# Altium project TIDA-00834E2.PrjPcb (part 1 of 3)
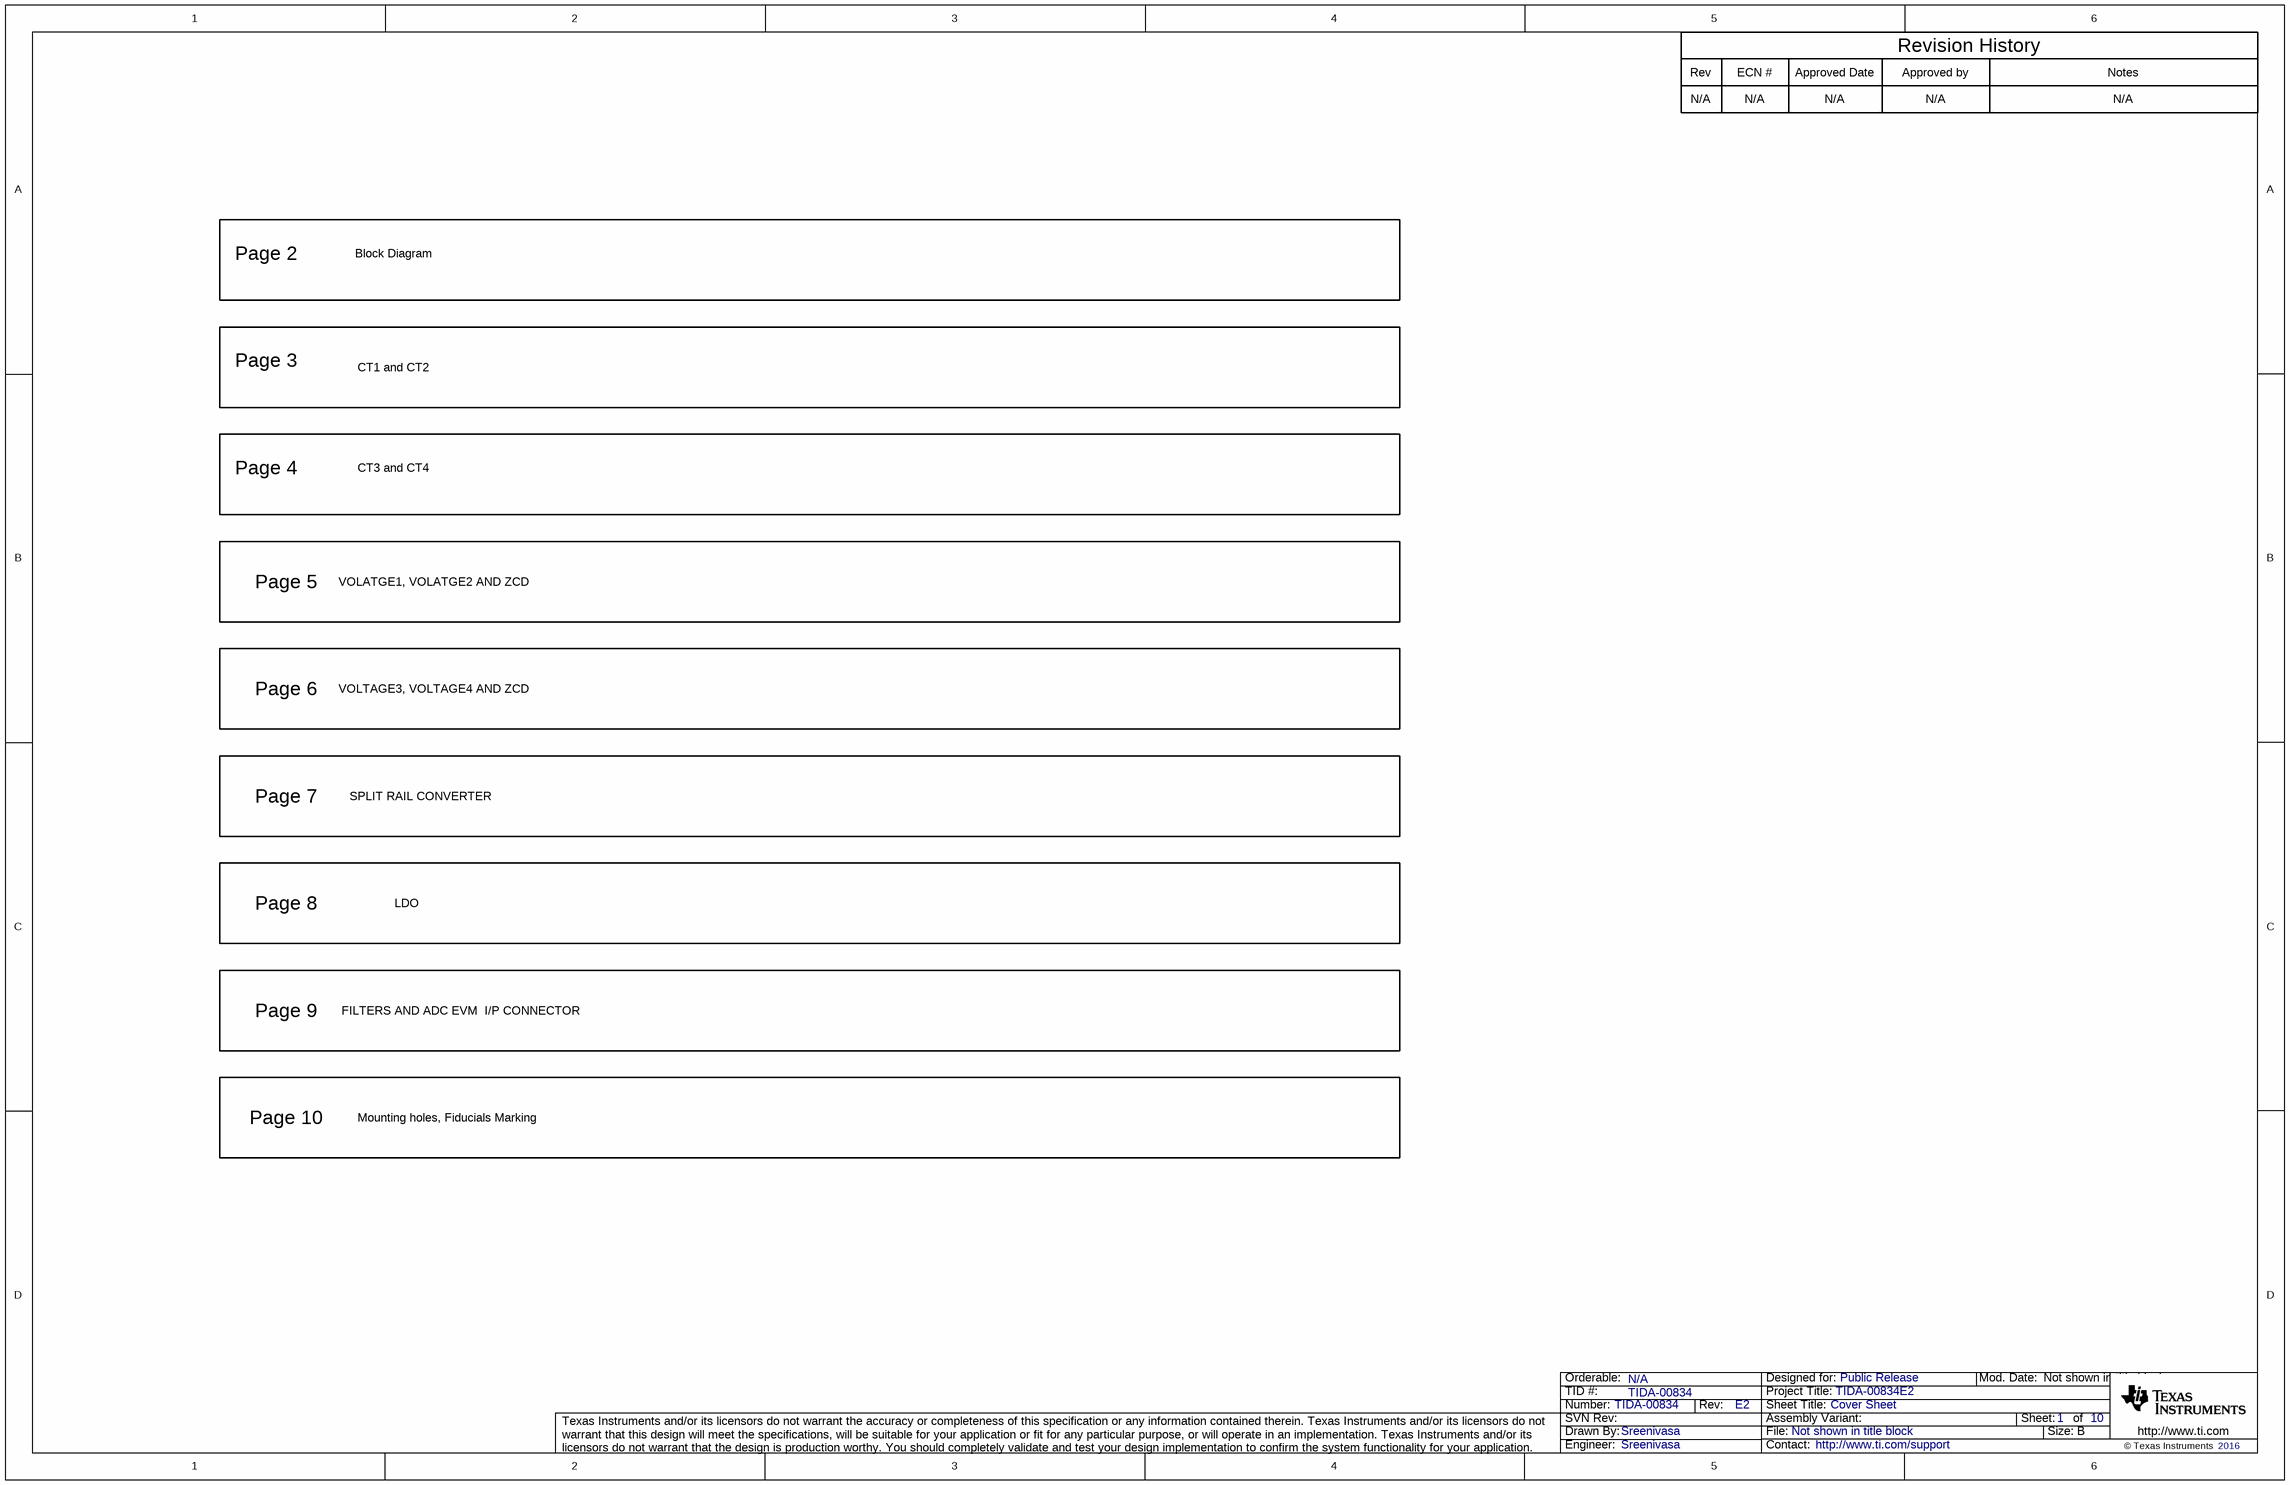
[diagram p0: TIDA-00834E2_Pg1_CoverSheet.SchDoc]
CopyrightYear: 2016; EVM_Orderable: N/A; PCB_Layout: Manjunath M; PCB_Rev: E2; PRJ_Customer: Public Release; PRJ_Engineer: Sreenivasa; PRJ_Number: TIDA-00834; PRJ_Title: TIDA-00834E2; SCH_Rev: E2; TechSupport: http://www.ti.com/support; TID: TIDA-00834
10 sheets, 589 parts. Net scope: flat (ports and power ports of the same name join across sheets).
Board file: TIDA-00834E2_PCB.PcbDoc
Sheets:
  TIDA-00834E2_Pg1_CoverSheet.SchDoc
  TIDA-00834E2_Pg2_Block Diagram.SchDoc
  TIDA-00834E2_Pg3_CT1_CT2.SchDoc
  TIDA-00834E2_Pg4_CT3_CT4.SchDoc
  TIDA-00834E2_Pg5_VOLTAGE.SchDoc
  TIDA-00834E2_Pg6_VOLTAGE2.SchDoc
  TIDA-00834E2_Pg7_Split Rail Converter.SchDoc
  TIDA-00834E2_Pg8_LDO.SchDoc
  TIDA-00834E2_Pg9_Filters.SchDoc
  TIDA-00834E2_Pg10_EVM_Hardware.SchDoc

## Sheet TIDA-00834E2_Pg1_CoverSheet.SchDoc: Cover Sheet
size 431 x 279 mm; Date: Not shown in title block; ApprovedBy: Not shown in title block; CheckedBy: Not shown in title block; Author: Not shown in title block; CompanyName: Not shown in title block; DrawnBy: Sreenivasa; Engineer: Not shown in title block; Organization: Not shown in title block; Address1: Not shown in title block; Address2: Not shown in title block; Address3: Not shown in title block; Address4: Not shown in title block; DocumentNumber: 1; Revision: Use project parameter SCH_Rev; SheetNumber: 1; SheetTotal: 10; PageSetup: Record=PageOptions¦CenterHorizontal=True¦CenterVertical=True¦PrintScale=1.00¦XCorrection=1.00¦YCorrection=1.00¦PrintKind=0¦BorderSize=5000000¦LeftOffset=0¦BottomOffset=0¦Orientation=2¦PaperLength=1000¦PaperWidth=1000¦Scale=100¦PaperSource=15¦PrintQuality=600¦MediaType=1¦DitherType=10¦PaperKind=Letter¦PrintScaleMode=1

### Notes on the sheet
- Rev
- N/A
- ECN #
- Approved Date
- Approved by
- Revision History
- Notes
- Page 2
- Block Diagram
- Page 3
- CT1 and CT2
- Page 4
- CT3 and CT4
- Page 5
- VOLATGE1, VOLATGE2 AND ZCD
- Page 6
- VOLTAGE3, VOLTAGE4 AND ZCD
- Page 7
- SPLIT RAIL CONVERTER
- Page 8
- LDO
- Page 9
- FILTERS AND ADC EVM  I/P CONNECTOR
- Page 10
- Mounting holes, Fiducials Marking

## Sheet TIDA-00834E2_Pg2_Block Diagram.SchDoc: Block Diagram
size 431 x 279 mm; Date: Not shown in title block; ApprovedBy: Not shown in title block; CheckedBy: Not shown in title block; Author: Not shown in title block; CompanyName: Not shown in title block; DrawnBy: Sreenivasa; Engineer: Not shown in title block; Organization: Not shown in title block; Address1: Not shown in title block; Address2: Not shown in title block; Address3: Not shown in title block; Address4: Not shown in title block; DocumentNumber: 1; Revision: Use project parameter SCH_Rev; SheetNumber: 2; SheetTotal: 10; PageSetup: Record=PageOptions¦CenterHorizontal=True¦CenterVertical=True¦PrintScale=1.00¦XCorrection=1.00¦YCorrection=1.00¦PrintKind=0¦BorderSize=5000000¦LeftOffset=0¦BottomOffset=0¦Orientation=2¦PaperLength=1000¦PaperWidth=1000¦Scale=100¦PaperSource=15¦PrintQuality=600¦MediaType=1¦DitherType=10¦PaperKind=Letter¦PrintScaleMode=1
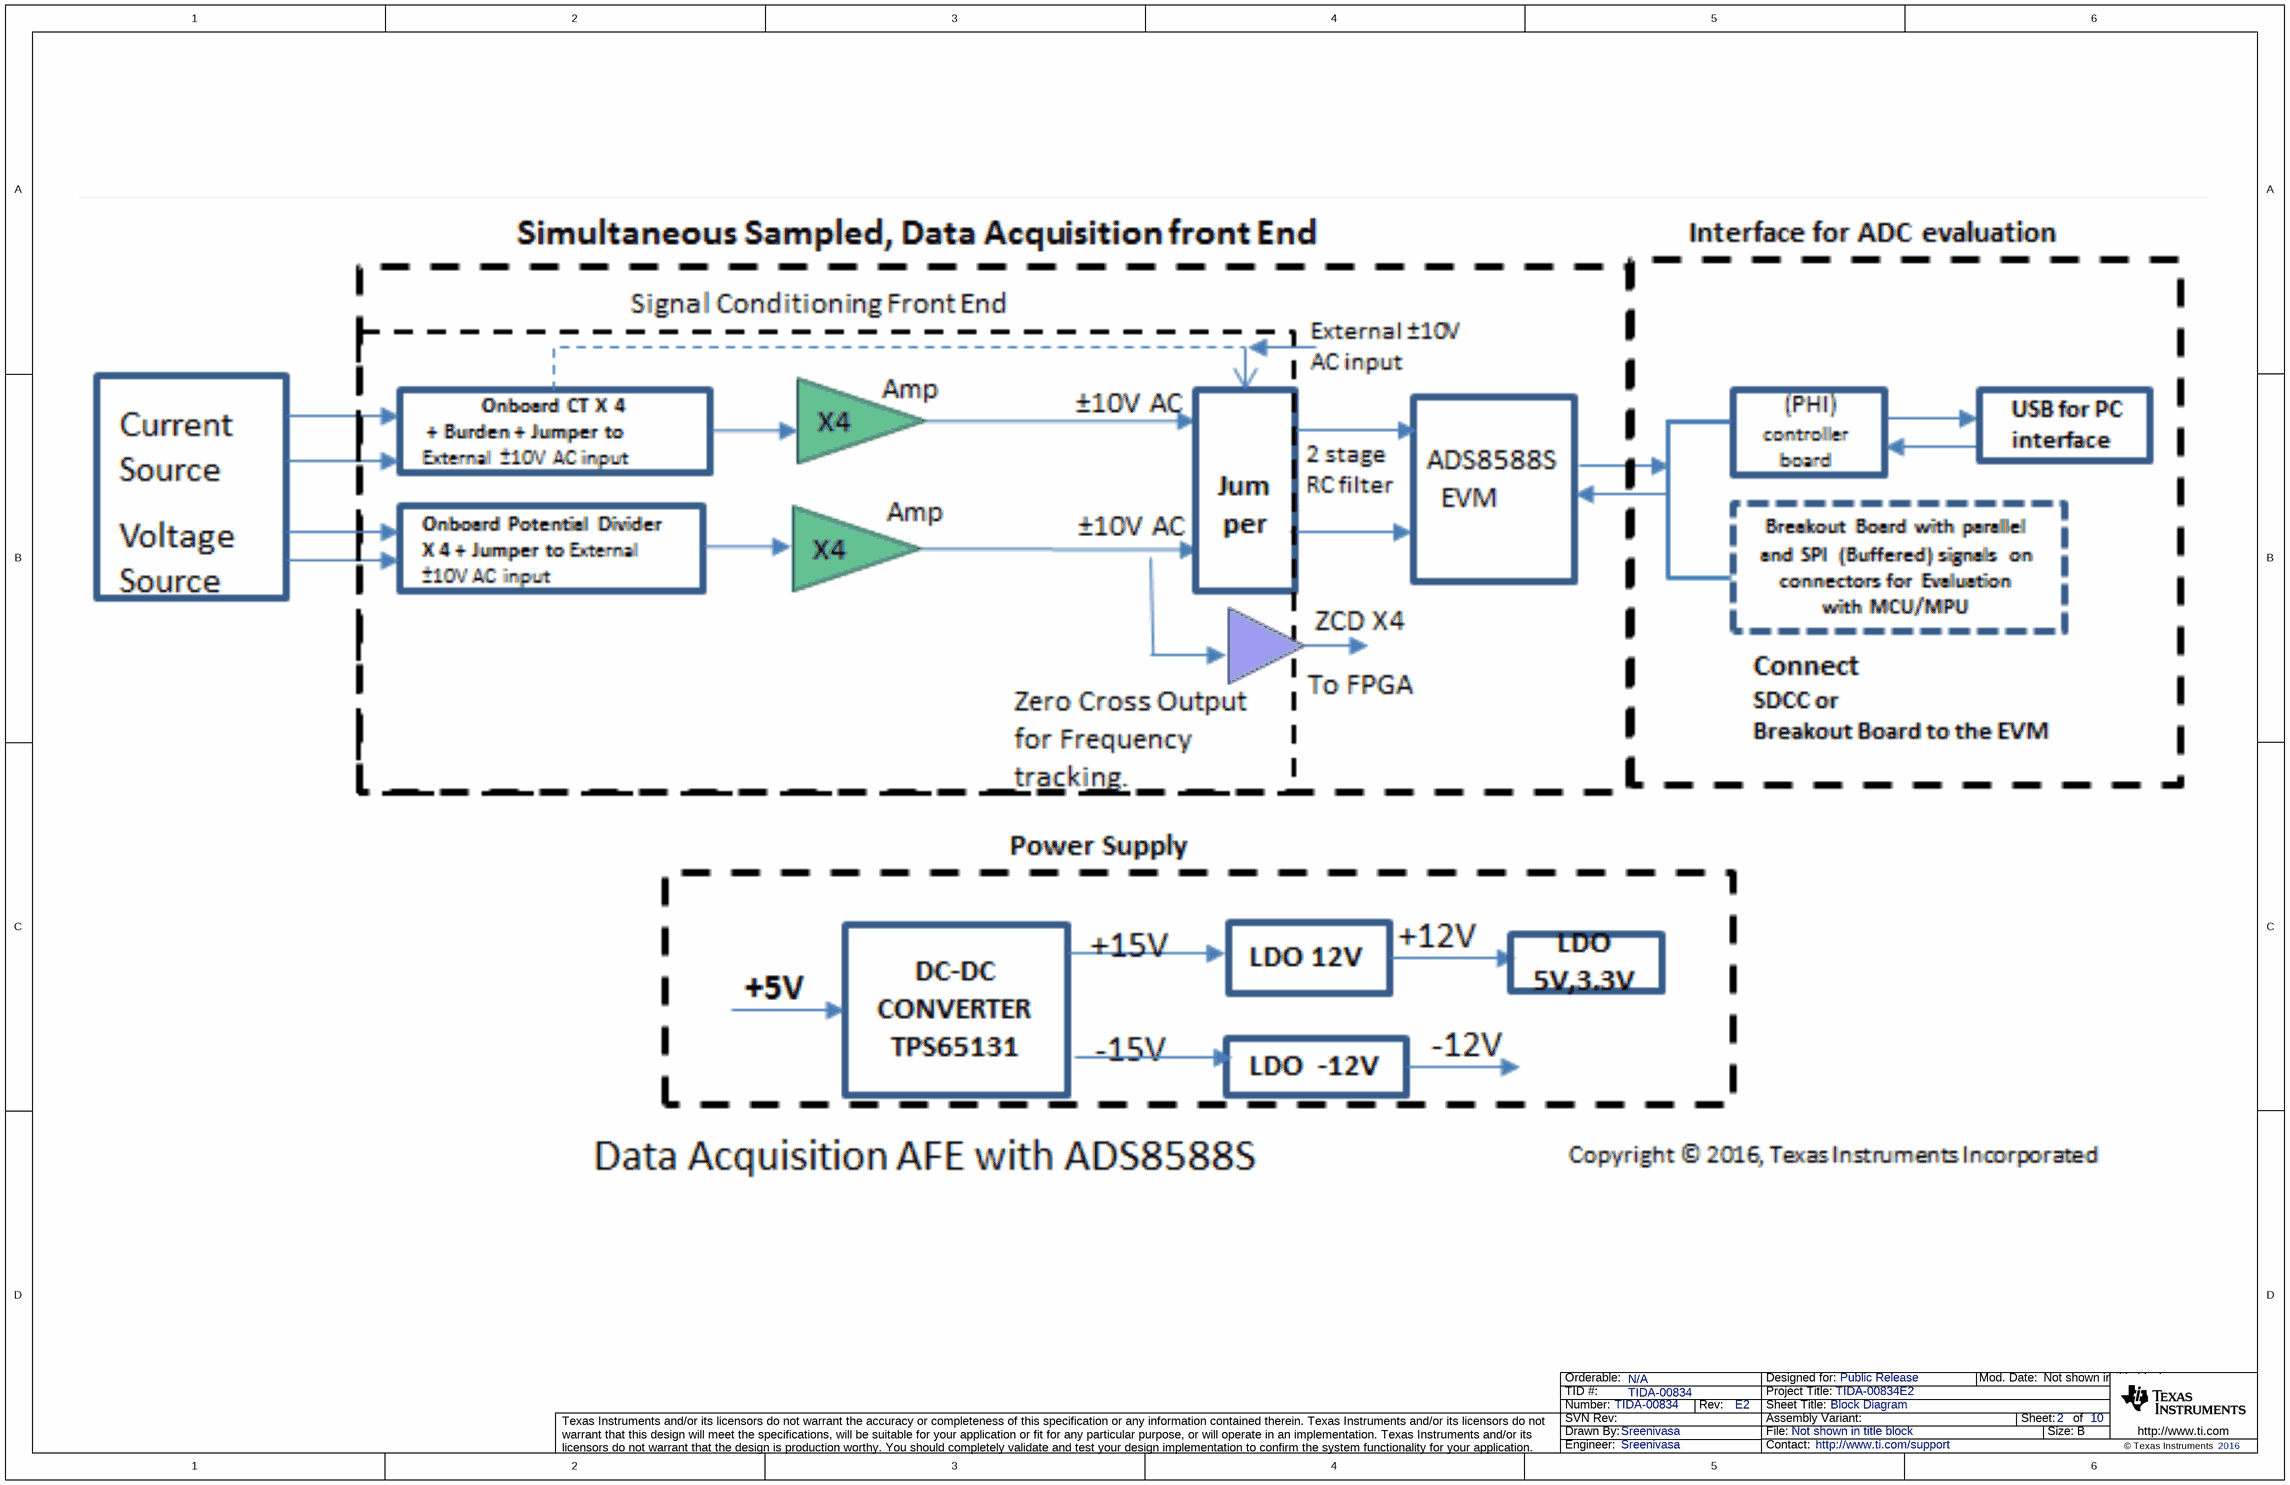
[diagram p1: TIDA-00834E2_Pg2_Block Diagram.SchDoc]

## Sheet TIDA-00834E2_Pg3_CT1_CT2.SchDoc: CT1 and CT2
size 431 x 279 mm; Date: Not shown in title block; ApprovedBy: Not shown in title block; CheckedBy: Not shown in title block; Author: Not shown in title block; CompanyName: Not shown in title block; DrawnBy: Sreenivasa; Engineer: Not shown in title block; Organization: Not shown in title block; Address1: Not shown in title block; Address2: Not shown in title block; Address3: Not shown in title block; Address4: Not shown in title block; DocumentNumber: 1; Revision: Use project parameter SCH_Rev; SheetNumber: 3; SheetTotal: 10; PageSetup: Record=PageOptions¦CenterHorizontal=True¦CenterVertical=True¦PrintScale=1.00¦XCorrection=1.00¦YCorrection=1.00¦PrintKind=0¦BorderSize=5000000¦LeftOffset=0¦BottomOffset=0¦Orientation=2¦PaperLength=1000¦PaperWidth=1000¦Scale=100¦PaperSource=15¦PrintQuality=600¦MediaType=1¦DitherType=10¦PaperKind=Letter¦PrintScaleMode=1
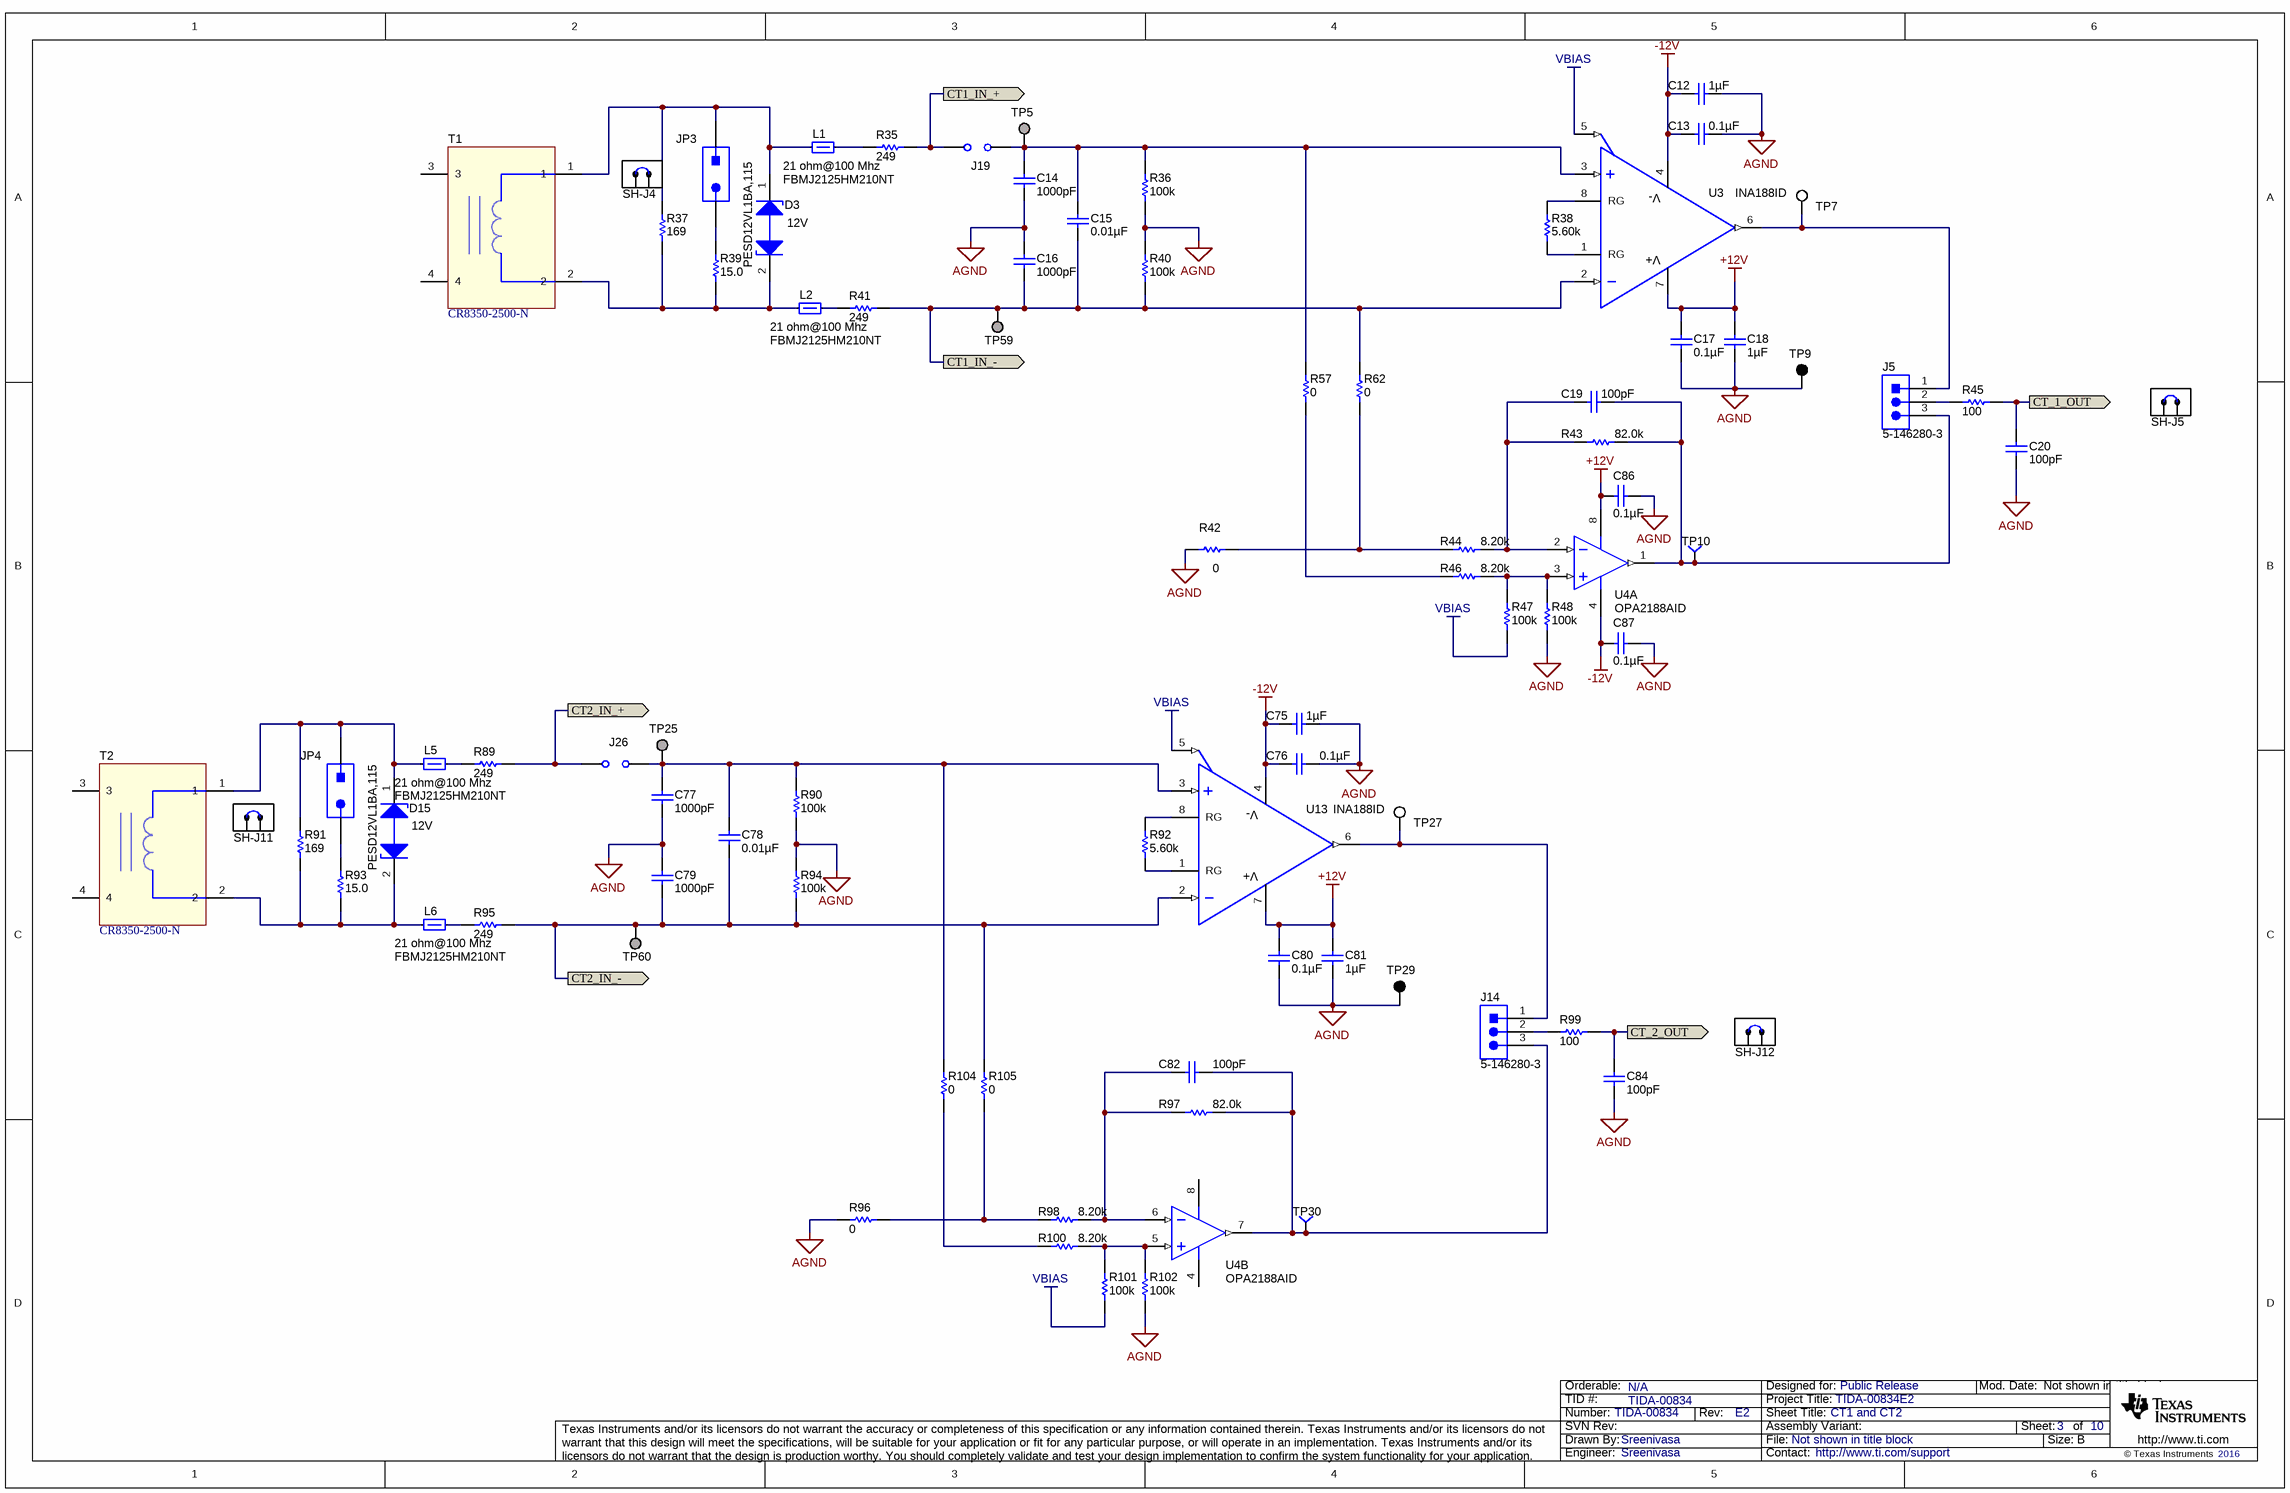
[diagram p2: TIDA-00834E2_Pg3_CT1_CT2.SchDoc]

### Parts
C12  ValueDisplayed: 1µF  [0603]  (hidden comment: GRM188R61C105KA93D)
C13  ValueDisplayed: 0.1µF  [0603]  (hidden comment: CGA3E2X8R1E104K080AA)
C14  ValueDisplayed: 1000pF  [0603]  (hidden comment: C0603X102K5RACTU)
C15  ValueDisplayed: 0.01µF  [0603]  (hidden comment: 06031C103KAT2A)
C16  ValueDisplayed: 1000pF  [0603]  (hidden comment: C0603X102K5RACTU)
C17  ValueDisplayed: 0.1µF  [0603]  (hidden comment: CGA3E2X8R1E104K080AA)
C18  ValueDisplayed: 1µF  [0603]  (hidden comment: GRM188R61C105KA93D)
C19  ValueDisplayed: 100pF  [0603]  (hidden comment: 06033C101KAT2A)
C20  ValueDisplayed: 100pF  [0603]  (hidden comment: 06033C101KAT2A)
C75  ValueDisplayed: 1µF  [0603]  (hidden comment: GRM188R61C105KA93D)
C76  ValueDisplayed: 0.1µF  [0603]  (hidden comment: CGA3E2X8R1E104K080AA)
C77  ValueDisplayed: 1000pF  [0603]  (hidden comment: C0603X102K5RACTU)
C78  ValueDisplayed: 0.01µF  [0603]  (hidden comment: 06031C103KAT2A)
C79  ValueDisplayed: 1000pF  [0603]  (hidden comment: C0603X102K5RACTU)
C80  ValueDisplayed: 0.1µF  [0603]  (hidden comment: CGA3E2X8R1E104K080AA)
C81  ValueDisplayed: 1µF  [0603]  (hidden comment: GRM188R61C105KA93D)
C82  ValueDisplayed: 100pF  [0603]  (hidden comment: 06033C101KAT2A)
C84  ValueDisplayed: 100pF  [0603]  (hidden comment: 06033C101KAT2A)
C86  ValueDisplayed: 0.1µF  [0603]  (hidden comment: CGA3E2X8R1E104K080AA)
C87  ValueDisplayed: 0.1µF  [0603]  (hidden comment: CGA3E2X8R1E104K080AA)
D3  value 12V  [SOD-323]  (hidden comment: PESD12VL1BA,115)
D15  value 12V  [SOD-323]  (hidden comment: PESD12VL1BA,115)
J5  5-146280-3  [TE_5-146280-3]
J14  5-146280-3  [TE_5-146280-3]
J19  JUMPER_2X100MIL  [HDR100_1X2]  (value not drawn)
J26  JUMPER_2X100MIL  [HDR100_1X2]  (value not drawn)
JP3  5-146280-2  [TSW-102-07-G-S]  (value not drawn)
JP4  5-146280-2  [TSW-102-07-G-S]  (value not drawn)
L1  value 21 ohm@100 Mhz  [0805_HV]  (hidden comment: FBMJ2125HM210NT)
L2  value 21 ohm@100 Mhz  [0805_HV]  (hidden comment: FBMJ2125HM210NT)
L5  value 21 ohm@100 Mhz  [0805_HV]  (hidden comment: FBMJ2125HM210NT)
L6  value 21 ohm@100 Mhz  [0805_HV]  (hidden comment: FBMJ2125HM210NT)
R35  ValueDisplayed: 249  [0603]  (hidden comment: RT0603BRD07249RL)
R36  ValueDisplayed: 100k  [0603]  (hidden comment: RC0603FR-07100KL)
R37  ValueDisplayed: 169  [0603]  (hidden comment: RC0603FR-07169RL)
R38  ValueDisplayed: 5.60k  [0603]  (hidden comment: RG1608P-562-B-T5)
R39  ValueDisplayed: 15.0  [0603]  (hidden comment: CRCW060315R0FKEA)
R40  ValueDisplayed: 100k  [0603]  (hidden comment: RC0603FR-07100KL)
R41  ValueDisplayed: 249  [0603]  (hidden comment: RT0603BRD07249RL)
R42  ValueDisplayed: 0  [0603]  (hidden comment: RC0603JR-070RL)
R43  ValueDisplayed: 82.0k  [0603]  (hidden comment: RG1608P-823-B-T5)
R44  ValueDisplayed: 8.20k  [0603]  (hidden comment: RC0603FR-078K2L)
R45  value 100  [0603]  (hidden comment: CRCW0603100RFKEA)
R46  ValueDisplayed: 8.20k  [0603]  (hidden comment: RC0603FR-078K2L)
R47  ValueDisplayed: 100k  [0603]  (hidden comment: RC0603FR-07100KL)
R48  ValueDisplayed: 100k  [0603]  (hidden comment: RC0603FR-07100KL)
R57  ValueDisplayed: 0  [0603]  (hidden comment: RC0603JR-070RL)
R62  ValueDisplayed: 0  [0603]  (hidden comment: RC0603JR-070RL)
R89  ValueDisplayed: 249  [0603]  (hidden comment: RT0603BRD07249RL)
R90  ValueDisplayed: 100k  [0603]  (hidden comment: RC0603FR-07100KL)
R91  ValueDisplayed: 169  [0603]  (hidden comment: RC0603FR-07169RL)
R92  ValueDisplayed: 5.60k  [0603]  (hidden comment: RG1608P-562-B-T5)
R93  ValueDisplayed: 15.0  [0603]  (hidden comment: CRCW060315R0FKEA)
R94  ValueDisplayed: 100k  [0603]  (hidden comment: RC0603FR-07100KL)
R95  ValueDisplayed: 249  [0603]  (hidden comment: RT0603BRD07249RL)
R96  ValueDisplayed: 0  [0603]  (hidden comment: RC0603JR-070RL)
R97  ValueDisplayed: 82.0k  [0603]  (hidden comment: RG1608P-823-B-T5)
R98  ValueDisplayed: 8.20k  [0603]  (hidden comment: RC0603FR-078K2L)
R99  value 100  [0603]  (hidden comment: CRCW0603100RFKEA)
R100  ValueDisplayed: 8.20k  [0603]  (hidden comment: RC0603FR-078K2L)
R101  ValueDisplayed: 100k  [0603]  (hidden comment: RC0603FR-07100KL)
R102  ValueDisplayed: 100k  [0603]  (hidden comment: RC0603FR-07100KL)
R104  ValueDisplayed: 0  [0603]  (hidden comment: RC0603JR-070RL)
R105  ValueDisplayed: 0  [0603]  (hidden comment: RC0603JR-070RL)
SH-J4  881545-2  [TE_881545-2]  (value not drawn)  (mechanical)
SH-J5  881545-2  [TE_881545-2]  (value not drawn)  (mechanical)
SH-J11  881545-2  [TE_881545-2]  (value not drawn)  (mechanical)
SH-J12  881545-2  [TE_881545-2]  (value not drawn)  (mechanical)
T1  CR8350-2500-N  [XFMR_CR8350-2500-N]
T2  CR8350-2500-N  [XFMR_CR8350-2500-N]
TP5  Suggest using a net name here  [Keystone1573-2]  (value not drawn)
TP7  5002  [Keystone5002]  (value not drawn)
TP9  5001  [Keystone5001]  (value not drawn)
TP10  TP-040_RND  [TP_H045P075]  (value not drawn)
TP25  Suggest using a net name here  [Keystone1573-2]  (value not drawn)
TP27  5002  [Keystone5002]  (value not drawn)
TP29  5001  [Keystone5001]  (value not drawn)
TP30  TP-040_RND  [TP_H045P075]  (value not drawn)
TP59  Suggest using a net name here  [Keystone1573-2]  (value not drawn)
TP60  Suggest using a net name here  [Keystone1573-2]  (value not drawn)
U3  INA188ID  [D0008A_N]
U4  OPA2188AID  [D0008A_N]  (parts A,B of 2)
U13  INA188ID  [D0008A_N]

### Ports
CT1_IN_+ (out), CT1_IN_- (out), CT2_IN_+ (out), CT2_IN_- (out), CT_1_OUT (out), CT_2_OUT (out)

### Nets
+12V: C17.1 C18.1 C80.1 C81.1 C86.1 U3.7(V+) U4.8(V+) U13.7(V+)
-12V: C12.1 C13.1 C75.1 C76.1 C87.1 U3.4(V-) U4.4(V-) U13.4(V-)
AGND: C12.2 C13.2 C14.2 C16.1 C17.2 C18.2 C20.2 C75.2 C76.2 C77.2 C79.1 C80.2 C81.2 C84.2 C86.2 C87.2 R36.1 R40.2 R42.1 R48.1 R90.1 R94.2 R96.2 R102.1 TP9.1 TP29.1
VBIAS: R47.1 R101.1 U3.5(REF) U13.5(REF)
CT1_IN_+: J19.2 R35.2 ; port CT1_IN_+
CT1_IN_-: C15.2 C16.2 R40.1 R41.2 R62.2 TP59.1 U3.2(IN-) ; port CT1_IN_-
CT2_IN_+: J26.2 R89.2 ; port CT2_IN_+
CT2_IN_-: C78.2 C79.2 R94.1 R95.2 R105.2 TP60.1 U13.2(IN-) ; port CT2_IN_-
CT_1_OUT: C20.1 R45.2 ; port CT_1_OUT
CT_2_OUT: C84.1 R99.2 ; port CT_2_OUT
NetC14_1: C14.1 C15.1 J19.1 R36.2 R57.2 TP5.1 U3.3(IN+)
NetC19_1: C19.1 R43.2 R44.1 U4.2(IN_A-)
NetC19_2: C19.2 J5.3 R43.1 TP10.1 U4.1(OUT_A)
NetC77_1: C77.1 C78.1 J26.1 R90.2 R104.2 TP25.1 U13.3(IN+)
NetC82_1: C82.1 R97.2 R98.1 U4.6(IN_B-)
NetC82_2: C82.2 J14.3 R97.1 TP30.1 U4.7(OUT_B)
NetD3_1: D3.1(K) JP3.1 L1.1 R37.2 T1.1
NetD3_2: D3.2(K) L2.1 R37.1 R39.1 T1.2
NetD15_1: D15.1(K) JP4.1 L5.1 R91.2 T2.1
NetD15_2: D15.2(K) L6.1 R91.1 R93.1 T2.2
NetJ5_1: J5.1 TP7.1 U3.6(OUT)
NetJ5_2: J5.2 R45.1
NetJ14_1: J14.1 TP27.1 U13.6(OUT)
NetJ14_2: J14.2 R99.1
NetJP3_2: JP3.2 R39.2
NetJP4_2: JP4.2 R93.2
NetL1_2: L1.2 R35.1
NetL2_2: L2.2 R41.1
NetL5_2: L5.2 R89.1
NetL6_2: L6.2 R95.1
NetR38_1: R38.1 U3.1(RG)
NetR38_2: R38.2 U3.8(RG)
NetR42_2: R42.2 R44.2 R62.1
NetR46_1: R46.1 R47.2 R48.2 U4.3(IN_A+)
NetR46_2: R46.2 R57.1
NetR92_1: R92.1 U13.1(RG)
NetR92_2: R92.2 U13.8(RG)
NetR96_1: R96.1 R98.2 R105.1
NetR100_1: R100.1 R101.2 R102.2 U4.5(IN_B+)
NetR100_2: R100.2 R104.1

Not connected (* = marked no-connect by the designer): T1 3 4; T2 3 4

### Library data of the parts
C12 C18 C75 C81 = C1608X5R1C105K: CAP, CERM, 1 µF, 16 V, +/- 10%, X5R, 0603; Manufacturer: Murata; Polarized: N; CompType: Capacitor; Value: 1uF; U/M: EA; Cap_F: 0.000001; Tolerance_%: 10; ESR_ohm: 0.0057; Value1: 0.0057 ohm; VDC_V: 16; Value2: 16V; TaMin_C: -55; TaMax_C: 85; AEC Category: Q200
C13 C17 C76 C80 C86 C87 = CGA3E2X8R1E104K080AA: CAP, CERM, 0.1 µF, 25 V, +/- 10%, X8R, AEC-Q200 Grade 0, 0603; Manufacturer: TDK; Polarized: N; CompType: Capacitor; Value: 0.1uF; U/M: EA; Cap_F: 0.0000001; Tolerance_%: 10; Value1: Unknown; VDC_V: 25; Value2: 25V; TaMin_C: -55; TaMax_C: 150; AEC Category: Q200; AEC Qualified: Y; AEC Grade: 0
C14 C16 C77 C79 = C0603X102K5RACTU: CAP, CERM, 1000 pF, 50 V, +/- 10%, X7R, 0603; Manufacturer: Kemet; Polarized: N; CompType: Capacitor; Value: 1000pF; U/M: EA; Cap_F: 0.000000001; Tolerance_%: 10; Value1: Unknown; VDC_V: 50; Value2: 50V; TaMin_C: -55; TaMax_C: 125; AEC Category: Q200
C15 C78 = 06031C103JAT2A: 10000pF 100V Ceramic Capacitor X7R 0603; Manufacturer: AVX; Polarized: N; Value: 0.01uF; U/M: EA; Cap_F: 0.00000001; Tolerance_%: 5; ESR_ohm: 0.098; Value1: 0.098 ohm; VDC_V: 100; TaMin_C: -55; TaMax_C: 125; AEC Category: Q200
C19 C20 C82 C84 = 06033C101KAT2A: CAP, CERM, 100pF, 25V, +/-10%, X7R, 0603; Manufacturer: AVX; Polarized: N; CompType: Capacitor; U/M: EA; Cap_F: 0.0000000001; Tolerance_%: 10; Value1: Unknown; VDC_V: 25; TaMin_C: -55; TaMax_C: 125
D3 D15 = PESD3V3L1BA: TVS DIODE 12VWM 37VC SOD323; Manufacturer: NXP Semiconductor; SymbolCreator: x0199378
J5 J14 = 5-146280-3: Header, 2.54mm, 3x1, Gold, TH; Manufacturer: TE Connectivity; SymbolCreator: a0799628; Pitch_mm: 2.54; Gender: Male; Shrouded: N; Row_Count: 1
J19 J26 = JUMPER_2X100MIL: Header, Male 2-pin, 100mil spacing,; Manufacturer: Sullins; PartNumber: PEC02SAAN; area: 20000; Value: PEC02SAAN
JP3 JP4 = TSW-102-07-G-S: Header, 100mil, 2x1, Gold, TH; Manufacturer: TE Connectivity; SymbolCreator: a0412235; U/M: EA
L1 L2 L5 L6 = FBMJ2125HM210NT: Ferrite Bead, 21 ohm @ 100 MHz, 6 A, 0805; Manufacturer: Taiyo Yuden; Imax_A: 6; DCR_ohm: 0.004; Value1: 0.004 ohm; Value2: 6A; ZTyp@100MHz_Ohm: 21
R35 R41 R89 R95 = RT0603BRD07249RL: RES, 249, 0.1%, 0.1 W, 0603; Manufacturer: Yageo America; CompType: Resistor; Value: 249; Value_Code: 249R; Tolerance_%: 0.1; Value2: 0.1W; VDC_V: 75; TempCo: 25 ppm/C; EIA_Code: E192; U/M: EA; AEC Category: Q200
R36 R40 R47 R48 R90 R94 R101 R102 = RC0603FR-07100KL: RES, 100 k, 1%, 0.1 W, 0603; Manufacturer: Yageo America; CompType: Resistor; Value: 100k; Res_ohm: 100000; Tolerance_%: 1; Power_W: 0.1; Value2: 0.1W; VDC_V: 150; TempCo: 200 ppm/C; EIA_Code: E96; U/M: EA; AEC Category: Q200
R37 R91 = RC0603FR-07169RL: RES, 169, 1%, 0.1 W, 0603; Manufacturer: Yageo America; CompType: Resistor; Value: 169; Value_Code: 169R; Tolerance_%: 1; Power_W: 0.1; Value2: 0.1W; VDC_V: 150; TempCo: 200 ppm/C; SizeArea_mm2: 1.28; SizeX_mm: 1.6; SizeY_mm: 0.8; EIA_Code: E96; U/M: EA; AEC Category: Q200
R38 R92 = RG1608P-562-B-T5: RES, 5.60 k, 0.1%, 0.1 W, 0603; Manufacturer: Susumu Co Ltd; CompType: Resistor; Value: 5.60k; Res_ohm: 5600; Value_Code: 5k60; Tolerance_%: 0.1; Value2: 0.1W; VDC_V: 75; TempCo: 25 ppm/C; SizeArea_mm2: 1.28; SizeX_mm: 1.6; SizeY_mm: 0.8; SizeZ_mm: 1; U/M: EA; AEC Category: Q200
R39 R93 = CRCW060315R0FKEA: RES, 15.0, 1%, 0.1 W, 0603; Manufacturer: Vishay-Dale; CompType: Resistor; Value: 15.0; Res_ohm: 15; Value_Code: 15R0; Tolerance_%: 1; Power_W: 0.1; Value2: 0.1W; VDC_V: 75; TempCo: 100 ppm/C; SizeArea_mm2: 1.28; SizeX_mm: 1.6; SizeY_mm: 0.8; EIA_Code: E96; U/M: EA; AEC Category: Q200
R42 R57 R62 R96 R104 R105 = RC0603JR-070RL: RES, 0, 5%, 0.1 W, 0603; Manufacturer: Yageo America; CompType: Resistor; Value: 0; Value_Code: 0000; Tolerance_%: 5; Power_W: 0.1; Value2: 0.1W; VDC_V: 50; TempCo: 200 ppm/C; EIA_Code: E24; U/M: EA; AEC Category: Q200
R43 R97 = RG1608P-823-B-T5: RES, 82.0 k, 0.1%, 0.1 W, 0603; Manufacturer: Susumu Co Ltd; CompType: Resistor; Value: 82.0k; Res_ohm: 82000; Value_Code: 82k0; Tolerance_%: 0.1; Value2: 0.1W; VDC_V: 75; TempCo: 25 ppm/C; SizeArea_mm2: 1.28; SizeX_mm: 1.6; SizeY_mm: 0.8; SizeZ_mm: 1; U/M: EA; AEC Category: Q200
R44 R46 R98 R100 = RC0603FR-078K2L: RES, 8.20 k, 1%, 0.1 W, 0603; Manufacturer: Yageo America; CompType: Resistor; Value: 8.20k; Res_ohm: 8200; Value_Code: 8k20; Tolerance_%: 1; Power_W: 0.1; Value2: 0.1W; VDC_V: 150; TempCo: 200 ppm/C; U/M: EA; AEC Category: Q200
R45 R99 = CRCW0603100RFKEA: RES, 100 ohm, 1%, 0.1W, 0603; Manufacturer: Vishay-Dale; CompType: Resistor; Value_Code: 100R; Tolerance_%: 1; Power_W: 0.1; VDC_V: 75; TempCo: 100 ppm/C; EIA_Code: E96; U/M: EA
SH-J4 SH-J5 SH-J11 SH-J12 = 881545-2: Shunt, 100mil, Gold plated, Black; Manufacturer: TE Connectivity
T1 T2 = CR8350-2500-N: CURRENT TRANSFORMER, 20-1 KHz, 57 OHM, VERTICAL, THRU-4P; Manufacturer: CR MAGNETICS; SymbolCreator: x0199378
TP5 TP25 TP59 TP60 = 1573-2: Terminal, Turret, TH, Double; Manufacturer: Keystone; CompType: Turret Terminal; U/M: EA
TP7 TP27 = 5002: Test Point, Miniature, White, TH; Manufacturer: Keystone; CompType: Test Point Loop; U/M: EA
TP9 TP29 = 5001: Test Point, Miniature, Black, TH; Manufacturer: Keystone; CompType: Test Point Loop; U/M: EA
TP10 TP30 = TP-040_RND: Test Point, O.040 Hole; Manufacturer: STD; Value: STD
U3 U13 = INA188D: INA188 Precision, Zero-Drift, Rail-to-Rail Out, High Voltage Instrumentation Amplifier, D0008A; Manufacturer: Texas Instruments; SymbolCreator: Altium; CompType: IC; U/M: EA
U4 = OPA2188AID: 0.03 uV/degC, 6 uV Vos, Low Noise, Rail-to-Rail Output, Zero-Drift Operational Amplifier, 4 to 36 V, -40 to 105 degC, 8-pin SOIC (D0008A), Green (RoHS & no Sb/Br); Manufacturer: Texas Instruments; Alternate PartNumber: Equivalent; CMRR(Min)(dB): 120; GBW(Typ)(MHz): 2; IIB(Max)(pA): 850; Iq per channel(Max)(mA): 0.475; Offset Drift(Typ)(uV/C): 0.03; Packing: TUBE; Rating: Catalog; Slew Rate(Typ)(V/us): 0.8; Sub Family: High Supply Voltage Amplifier (>=30V), Low Noise Amp (<=10nV/rtHz), Low Offset Voltage Amplifier (<=500uV), Low Power Amp (<=500uA), Precision Amplifier, Zero Drift Precision Amplifier; Total Supply Voltage(Max)(+5V is 5, +/-5V is 10): 36; Total Supply Voltage(Min)(+5V is 5, +/-5V is 10): 4; Vio (25C)(Max)(mV): 0.025

## Sheet TIDA-00834E2_Pg4_CT3_CT4.SchDoc: CT3 and CT4
size 431 x 279 mm; Date: Not shown in title block; ApprovedBy: Not shown in title block; CheckedBy: Not shown in title block; Author: Not shown in title block; CompanyName: Not shown in title block; DrawnBy: Sreenivasa; Engineer: Not shown in title block; Organization: Not shown in title block; Address1: Not shown in title block; Address2: Not shown in title block; Address3: Not shown in title block; Address4: Not shown in title block; DocumentNumber: 1; Revision: Use project parameter SCH_Rev; SheetNumber: 4; SheetTotal: 10; PageSetup: Record=PageOptions¦CenterHorizontal=True¦CenterVertical=True¦PrintScale=1.00¦XCorrection=1.00¦YCorrection=1.00¦PrintKind=0¦BorderSize=5000000¦LeftOffset=0¦BottomOffset=0¦Orientation=2¦PaperLength=1000¦PaperWidth=1000¦Scale=100¦PaperSource=15¦PrintQuality=600¦MediaType=1¦DitherType=10¦PaperKind=Letter¦PrintScaleMode=1
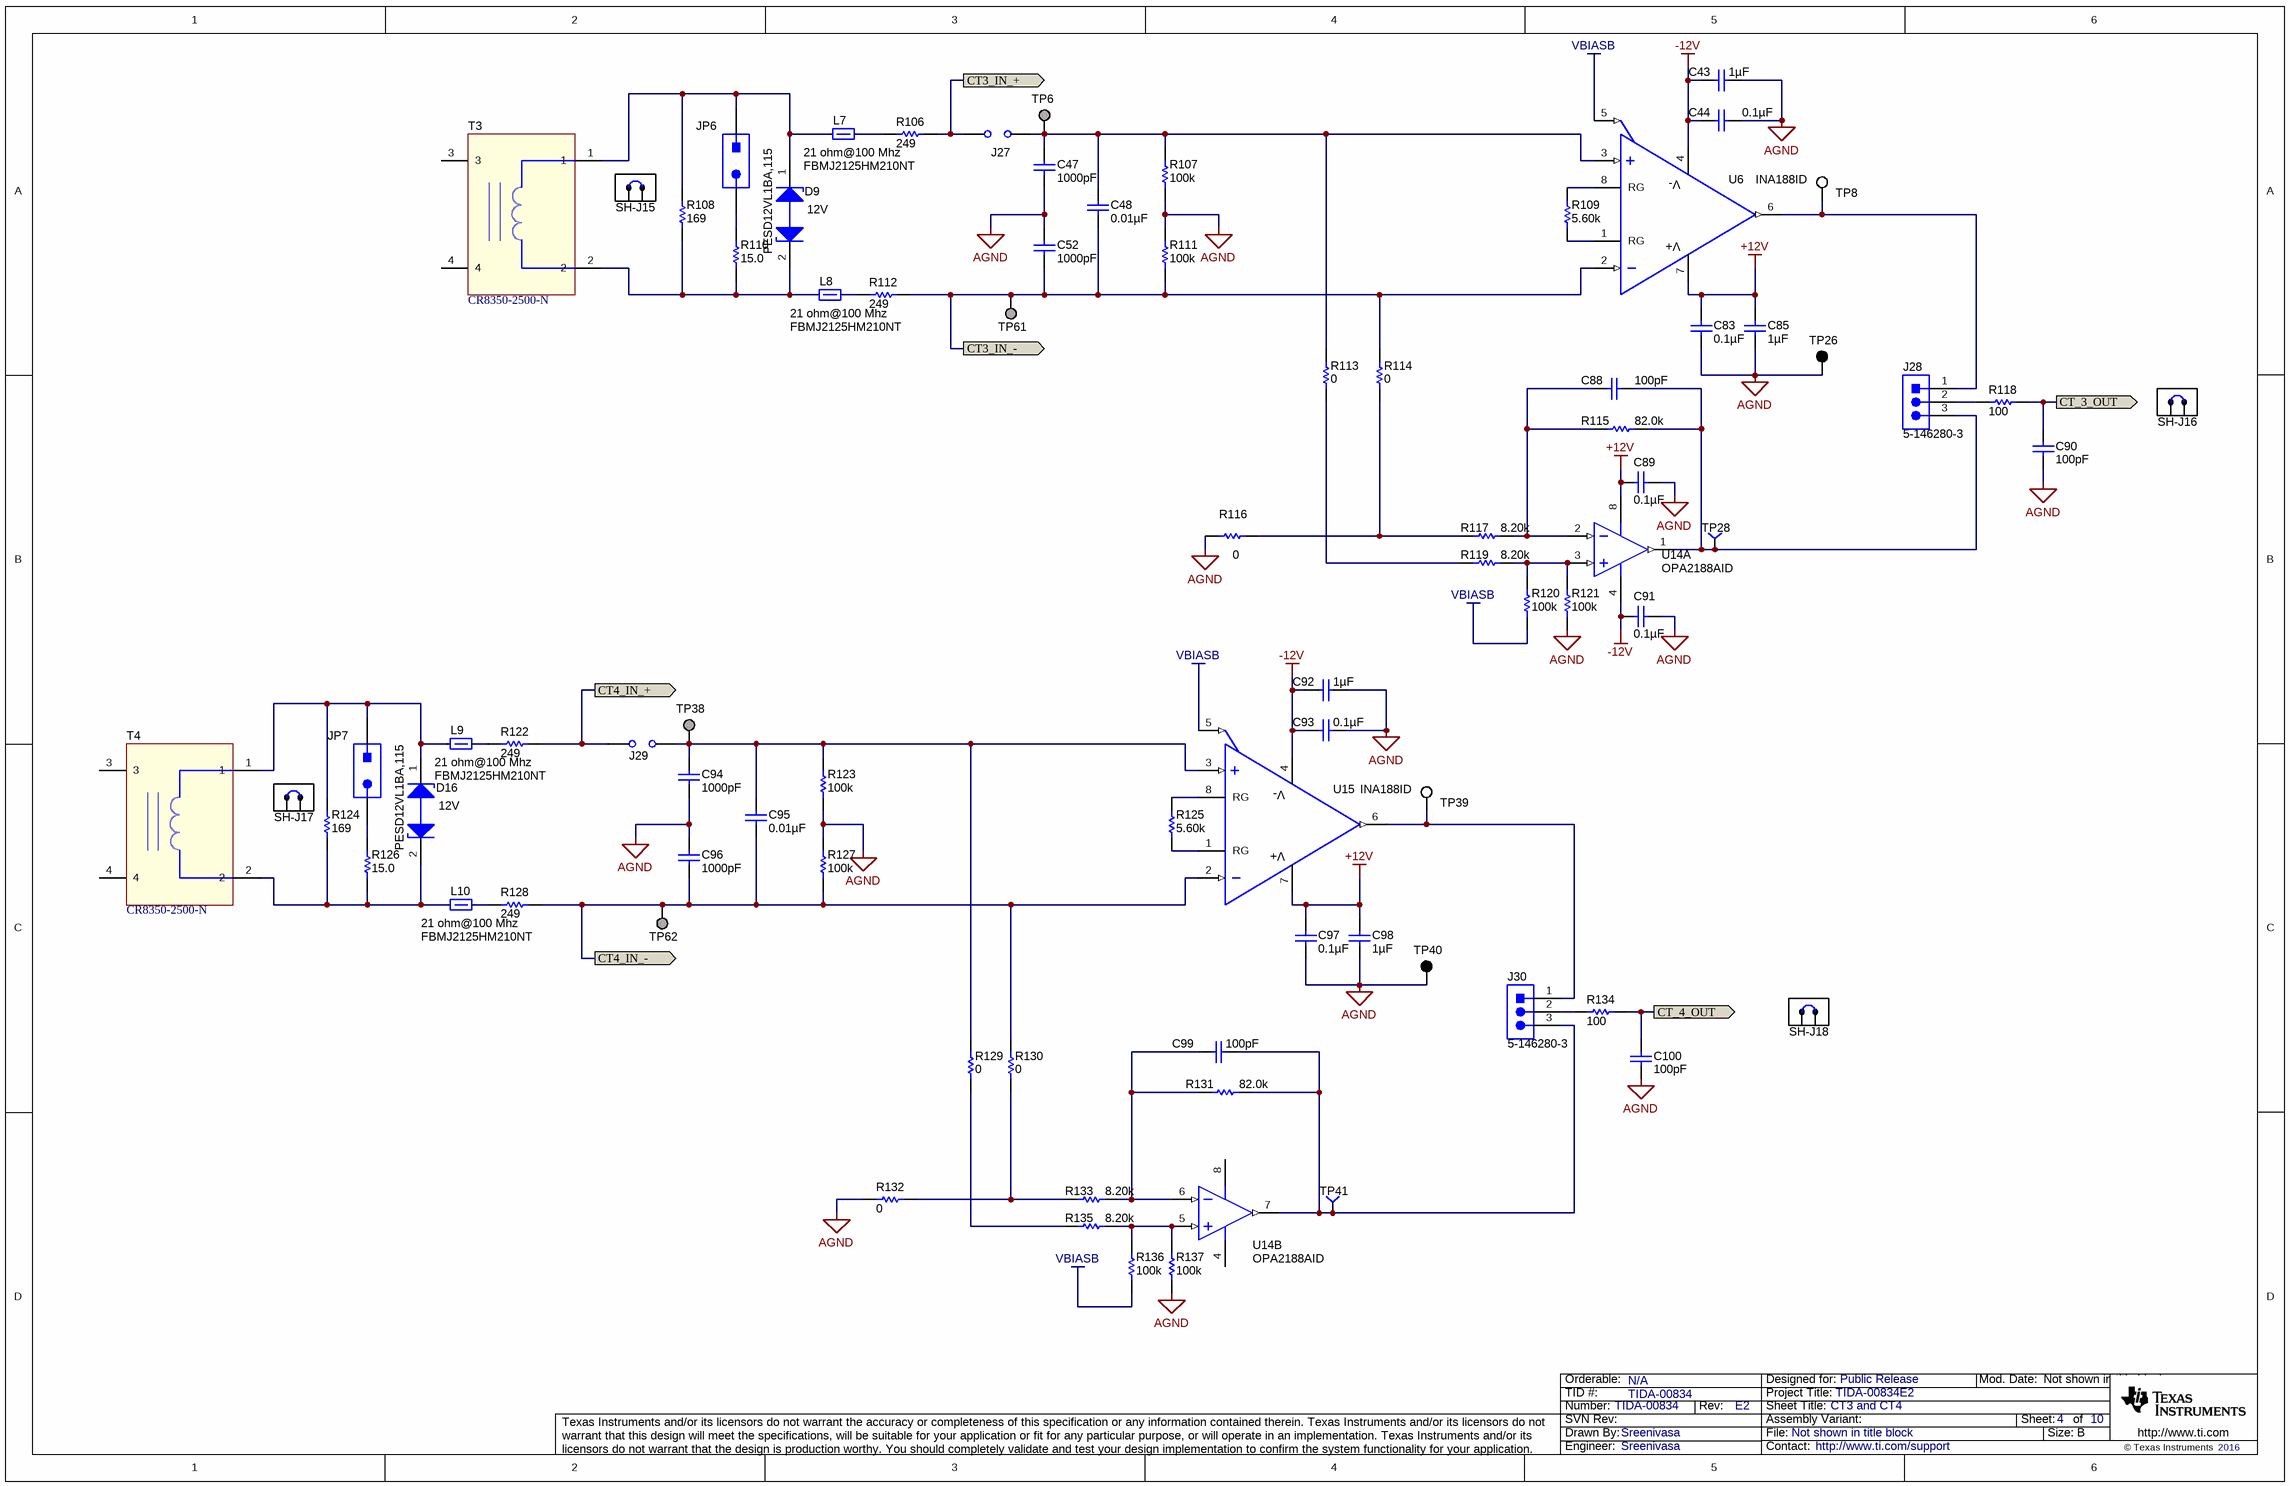
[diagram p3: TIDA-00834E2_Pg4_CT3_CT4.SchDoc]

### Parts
C43  ValueDisplayed: 1µF  [0603]  (hidden comment: GRM188R61C105KA93D)
C44  ValueDisplayed: 0.1µF  [0603]  (hidden comment: CGA3E2X8R1E104K080AA)
C47  ValueDisplayed: 1000pF  [0603]  (hidden comment: C0603X102K5RACTU)
C48  ValueDisplayed: 0.01µF  [0603]  (hidden comment: 06031C103KAT2A)
C52  ValueDisplayed: 1000pF  [0603]  (hidden comment: C0603X102K5RACTU)
C83  ValueDisplayed: 0.1µF  [0603]  (hidden comment: CGA3E2X8R1E104K080AA)
C85  ValueDisplayed: 1µF  [0603]  (hidden comment: GRM188R61C105KA93D)
C88  ValueDisplayed: 100pF  [0603]  (hidden comment: 06033C101KAT2A)
C89  ValueDisplayed: 0.1µF  [0603]  (hidden comment: CGA3E2X8R1E104K080AA)
C90  ValueDisplayed: 100pF  [0603]  (hidden comment: 06033C101KAT2A)
C91  ValueDisplayed: 0.1µF  [0603]  (hidden comment: CGA3E2X8R1E104K080AA)
C92  ValueDisplayed: 1µF  [0603]  (hidden comment: GRM188R61C105KA93D)
C93  ValueDisplayed: 0.1µF  [0603]  (hidden comment: CGA3E2X8R1E104K080AA)
C94  ValueDisplayed: 1000pF  [0603]  (hidden comment: C0603X102K5RACTU)
C95  ValueDisplayed: 0.01µF  [0603]  (hidden comment: 06031C103KAT2A)
C96  ValueDisplayed: 1000pF  [0603]  (hidden comment: C0603X102K5RACTU)
C97  ValueDisplayed: 0.1µF  [0603]  (hidden comment: CGA3E2X8R1E104K080AA)
C98  ValueDisplayed: 1µF  [0603]  (hidden comment: GRM188R61C105KA93D)
C99  ValueDisplayed: 100pF  [0603]  (hidden comment: 06033C101KAT2A)
C100  ValueDisplayed: 100pF  [0603]  (hidden comment: 06033C101KAT2A)
D9  value 12V  [SOD-323]  (hidden comment: PESD12VL1BA,115)
D16  value 12V  [SOD-323]  (hidden comment: PESD12VL1BA,115)
J27  JUMPER_2X100MIL  [HDR100_1X2]  (value not drawn)
J28  5-146280-3  [TE_5-146280-3]
J29  JUMPER_2X100MIL  [HDR100_1X2]  (value not drawn)
J30  5-146280-3  [TE_5-146280-3]
JP6  5-146280-2  [TSW-102-07-G-S]  (value not drawn)
JP7  5-146280-2  [TSW-102-07-G-S]  (value not drawn)
L7  value 21 ohm@100 Mhz  [0805_HV]  (hidden comment: FBMJ2125HM210NT)
L8  value 21 ohm@100 Mhz  [0805_HV]  (hidden comment: FBMJ2125HM210NT)
L9  value 21 ohm@100 Mhz  [0805_HV]  (hidden comment: FBMJ2125HM210NT)
L10  value 21 ohm@100 Mhz  [0805_HV]  (hidden comment: FBMJ2125HM210NT)
R106  ValueDisplayed: 249  [0603]  (hidden comment: RT0603BRD07249RL)
R107  ValueDisplayed: 100k  [0603]  (hidden comment: RC0603FR-07100KL)
R108  ValueDisplayed: 169  [0603]  (hidden comment: RC0603FR-07169RL)
R109  ValueDisplayed: 5.60k  [0603]  (hidden comment: RG1608P-562-B-T5)
R110  ValueDisplayed: 15.0  [0603]  (hidden comment: CRCW060315R0FKEA)
R111  ValueDisplayed: 100k  [0603]  (hidden comment: RC0603FR-07100KL)
R112  ValueDisplayed: 249  [0603]  (hidden comment: RT0603BRD07249RL)
R113  ValueDisplayed: 0  [0603]  (hidden comment: RC0603JR-070RL)
R114  ValueDisplayed: 0  [0603]  (hidden comment: RC0603JR-070RL)
R115  ValueDisplayed: 82.0k  [0603]  (hidden comment: RG1608P-823-B-T5)
R116  ValueDisplayed: 0  [0603]  (hidden comment: RC0603JR-070RL)
R117  ValueDisplayed: 8.20k  [0603]  (hidden comment: RC0603FR-078K2L)
R118  value 100  [0603]  (hidden comment: CRCW0603100RFKEA)
R119  ValueDisplayed: 8.20k  [0603]  (hidden comment: RC0603FR-078K2L)
R120  ValueDisplayed: 100k  [0603]  (hidden comment: RC0603FR-07100KL)
R121  ValueDisplayed: 100k  [0603]  (hidden comment: RC0603FR-07100KL)
R122  ValueDisplayed: 249  [0603]  (hidden comment: RT0603BRD07249RL)
R123  ValueDisplayed: 100k  [0603]  (hidden comment: RC0603FR-07100KL)
R124  ValueDisplayed: 169  [0603]  (hidden comment: RC0603FR-07169RL)
R125  ValueDisplayed: 5.60k  [0603]  (hidden comment: RG1608P-562-B-T5)
R126  ValueDisplayed: 15.0  [0603]  (hidden comment: CRCW060315R0FKEA)
R127  ValueDisplayed: 100k  [0603]  (hidden comment: RC0603FR-07100KL)
R128  ValueDisplayed: 249  [0603]  (hidden comment: RT0603BRD07249RL)
R129  ValueDisplayed: 0  [0603]  (hidden comment: RC0603JR-070RL)
R130  ValueDisplayed: 0  [0603]  (hidden comment: RC0603JR-070RL)
R131  ValueDisplayed: 82.0k  [0603]  (hidden comment: RG1608P-823-B-T5)
R132  ValueDisplayed: 0  [0603]  (hidden comment: RC0603JR-070RL)
R133  ValueDisplayed: 8.20k  [0603]  (hidden comment: RC0603FR-078K2L)
R134  value 100  [0603]  (hidden comment: CRCW0603100RFKEA)
R135  ValueDisplayed: 8.20k  [0603]  (hidden comment: RC0603FR-078K2L)
R136  ValueDisplayed: 100k  [0603]  (hidden comment: RC0603FR-07100KL)
R137  ValueDisplayed: 100k  [0603]  (hidden comment: RC0603FR-07100KL)
SH-J15  881545-2  [TE_881545-2]  (value not drawn)  (mechanical)
SH-J16  881545-2  [TE_881545-2]  (value not drawn)  (mechanical)
SH-J17  881545-2  [TE_881545-2]  (value not drawn)  (mechanical)
SH-J18  881545-2  [TE_881545-2]  (value not drawn)  (mechanical)
T3  CR8350-2500-N  [XFMR_CR8350-2500-N]
T4  CR8350-2500-N  [XFMR_CR8350-2500-N]
TP6  Suggest using a net name here  [Keystone1573-2]  (value not drawn)
TP8  5002  [Keystone5002]  (value not drawn)
TP26  5001  [Keystone5001]  (value not drawn)
TP28  TP-040_RND  [TP_H045P075]  (value not drawn)
TP38  Suggest using a net name here  [Keystone1573-2]  (value not drawn)
TP39  5002  [Keystone5002]  (value not drawn)
TP40  5001  [Keystone5001]  (value not drawn)
TP41  TP-040_RND  [TP_H045P075]  (value not drawn)
TP61  Suggest using a net name here  [Keystone1573-2]  (value not drawn)
TP62  Suggest using a net name here  [Keystone1573-2]  (value not drawn)
U6  INA188ID  [D0008A_N]
U14  OPA2188AID  [D0008A_N]  (parts A,B of 2)
U15  INA188ID  [D0008A_N]

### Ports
CT3_IN_+ (out), CT3_IN_- (out), CT4_IN_+ (out), CT4_IN_- (out), CT_3_OUT (out), CT_4_OUT (out)

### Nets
+12V: C83.1 C85.1 C89.1 C97.1 C98.1 U6.7(V+) U14.8(V+) U15.7(V+)
-12V: C43.1 C44.1 C91.1 C92.1 C93.1 U6.4(V-) U14.4(V-) U15.4(V-)
AGND: C43.2 C44.2 C47.2 C52.1 C83.2 C85.2 C89.2 C90.2 C91.2 C92.2 C93.2 C94.2 C96.1 C97.2 C98.2 C100.2 R107.1 R111.2 R116.1 R121.1 R123.1 R127.2 R132.2 R137.1 TP26.1 TP40.1
VBIASB: R120.1 R136.1 U6.5(REF) U15.5(REF)
CT3_IN_+: J27.2 R106.2 ; port CT3_IN_+
CT3_IN_-: C48.2 C52.2 R111.1 R112.2 R114.2 TP61.1 U6.2(IN-) ; port CT3_IN_-
CT4_IN_+: J29.2 R122.2 ; port CT4_IN_+
CT4_IN_-: C95.2 C96.2 R127.1 R128.2 R130.2 TP62.1 U15.2(IN-) ; port CT4_IN_-
CT_3_OUT: C90.1 R118.2 ; port CT_3_OUT
CT_4_OUT: C100.1 R134.2 ; port CT_4_OUT
NetC47_1: C47.1 C48.1 J27.1 R107.2 R113.2 TP6.1 U6.3(IN+)
NetC88_1: C88.1 R115.2 R117.1 U14.2(IN_A-)
NetC88_2: C88.2 J28.3 R115.1 TP28.1 U14.1(OUT_A)
NetC94_1: C94.1 C95.1 J29.1 R123.2 R129.2 TP38.1 U15.3(IN+)
NetC99_1: C99.1 R131.2 R133.1 U14.6(IN_B-)
NetC99_2: C99.2 J30.3 R131.1 TP41.1 U14.7(OUT_B)
NetD9_1: D9.1(K) JP6.1 L7.1 R108.2 T3.1
NetD9_2: D9.2(K) L8.1 R108.1 R110.1 T3.2
NetD16_1: D16.1(K) JP7.1 L9.1 R124.2 T4.1
NetD16_2: D16.2(K) L10.1 R124.1 R126.1 T4.2
NetJ28_1: J28.1 TP8.1 U6.6(OUT)
NetJ28_2: J28.2 R118.1
NetJ30_1: J30.1 TP39.1 U15.6(OUT)
NetJ30_2: J30.2 R134.1
NetJP6_2: JP6.2 R110.2
NetJP7_2: JP7.2 R126.2
NetL7_2: L7.2 R106.1
NetL8_2: L8.2 R112.1
NetL9_2: L9.2 R122.1
NetL10_2: L10.2 R128.1
NetR109_1: R109.1 U6.1(RG)
NetR109_2: R109.2 U6.8(RG)
NetR113_1: R113.1 R119.2
NetR114_1: R114.1 R116.2 R117.2
NetR119_1: R119.1 R120.2 R121.2 U14.3(IN_A+)
NetR125_1: R125.1 U15.1(RG)
NetR125_2: R125.2 U15.8(RG)
NetR129_1: R129.1 R135.2
NetR130_1: R130.1 R132.1 R133.2
NetR135_1: R135.1 R136.2 R137.2 U14.5(IN_B+)

Not connected (* = marked no-connect by the designer): T3 3 4; T4 3 4

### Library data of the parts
C43 C85 C92 C98 = C1608X5R1C105K: as C12 on sheet TIDA-00834E2_Pg3_CT1_CT2
C44 C83 C89 C91 C93 C97 = CGA3E2X8R1E104K080AA: as C13 on sheet TIDA-00834E2_Pg3_CT1_CT2
C47 C52 C94 C96 = C0603X102K5RACTU: as C14 on sheet TIDA-00834E2_Pg3_CT1_CT2
C48 C95 = 06031C103JAT2A: as C15 on sheet TIDA-00834E2_Pg3_CT1_CT2
C88 C90 C99 C100 = 06033C101KAT2A: as C19 on sheet TIDA-00834E2_Pg3_CT1_CT2
D9 D16 = PESD3V3L1BA: as D3 on sheet TIDA-00834E2_Pg3_CT1_CT2
J27 J29 = JUMPER_2X100MIL: as J19 on sheet TIDA-00834E2_Pg3_CT1_CT2
J28 J30 = 5-146280-3: as J5 on sheet TIDA-00834E2_Pg3_CT1_CT2
JP6 JP7 = TSW-102-07-G-S: as JP3 on sheet TIDA-00834E2_Pg3_CT1_CT2
L7-L10 = FBMJ2125HM210NT: as L1 on sheet TIDA-00834E2_Pg3_CT1_CT2
R106 R112 R122 R128 = RT0603BRD07249RL: as R35 on sheet TIDA-00834E2_Pg3_CT1_CT2
R107 R111 R120 R121 R123 R127 R136 R137 = RC0603FR-07100KL: as R36 on sheet TIDA-00834E2_Pg3_CT1_CT2
R108 R124 = RC0603FR-07169RL: as R37 on sheet TIDA-00834E2_Pg3_CT1_CT2
R109 R125 = RG1608P-562-B-T5: as R38 on sheet TIDA-00834E2_Pg3_CT1_CT2
R110 R126 = CRCW060315R0FKEA: as R39 on sheet TIDA-00834E2_Pg3_CT1_CT2
R113 R114 R116 R129 R130 R132 = RC0603JR-070RL: as R42 on sheet TIDA-00834E2_Pg3_CT1_CT2
R115 R131 = RG1608P-823-B-T5: as R43 on sheet TIDA-00834E2_Pg3_CT1_CT2
R117 R119 R133 R135 = RC0603FR-078K2L: as R44 on sheet TIDA-00834E2_Pg3_CT1_CT2
R118 R134 = CRCW0603100RFKEA: as R45 on sheet TIDA-00834E2_Pg3_CT1_CT2
SH-J15-SH-J18 = 881545-2: as SH-J4 on sheet TIDA-00834E2_Pg3_CT1_CT2
T3 T4 = CR8350-2500-N: as T1 on sheet TIDA-00834E2_Pg3_CT1_CT2
TP6 TP38 TP61 TP62 = 1573-2: as TP5 on sheet TIDA-00834E2_Pg3_CT1_CT2
TP8 TP39 = 5002: as TP7 on sheet TIDA-00834E2_Pg3_CT1_CT2
TP26 TP40 = 5001: as TP9 on sheet TIDA-00834E2_Pg3_CT1_CT2
TP28 TP41 = TP-040_RND: as TP10 on sheet TIDA-00834E2_Pg3_CT1_CT2
U6 U15 = INA188D: as U3 on sheet TIDA-00834E2_Pg3_CT1_CT2
U14 = OPA2188AID: as U4 on sheet TIDA-00834E2_Pg3_CT1_CT2

## Sheet TIDA-00834E2_Pg5_VOLTAGE.SchDoc: VOLATGE1, VOLATGE2 AND ZCD
size 431 x 279 mm; Date: Not shown in title block; ApprovedBy: Not shown in title block; CheckedBy: Not shown in title block; Author: Not shown in title block; CompanyName: Not shown in title block; DrawnBy: Sreenivasa; Engineer: Not shown in title block; Organization: Not shown in title block; Address1: Not shown in title block; Address2: Not shown in title block; Address3: Not shown in title block; Address4: Not shown in title block; DocumentNumber: 1; Revision: Use project parameter SCH_Rev; SheetNumber: 5; SheetTotal: 10; PageSetup: Record=PageOptions¦CenterHorizontal=True¦CenterVertical=True¦PrintScale=1.00¦XCorrection=1.00¦YCorrection=1.00¦PrintKind=0¦BorderSize=5000000¦LeftOffset=0¦BottomOffset=0¦Orientation=2¦PaperLength=1000¦PaperWidth=1000¦Scale=100¦PaperSource=15¦PrintQuality=600¦MediaType=1¦DitherType=10¦PaperKind=Letter¦PrintScaleMode=1
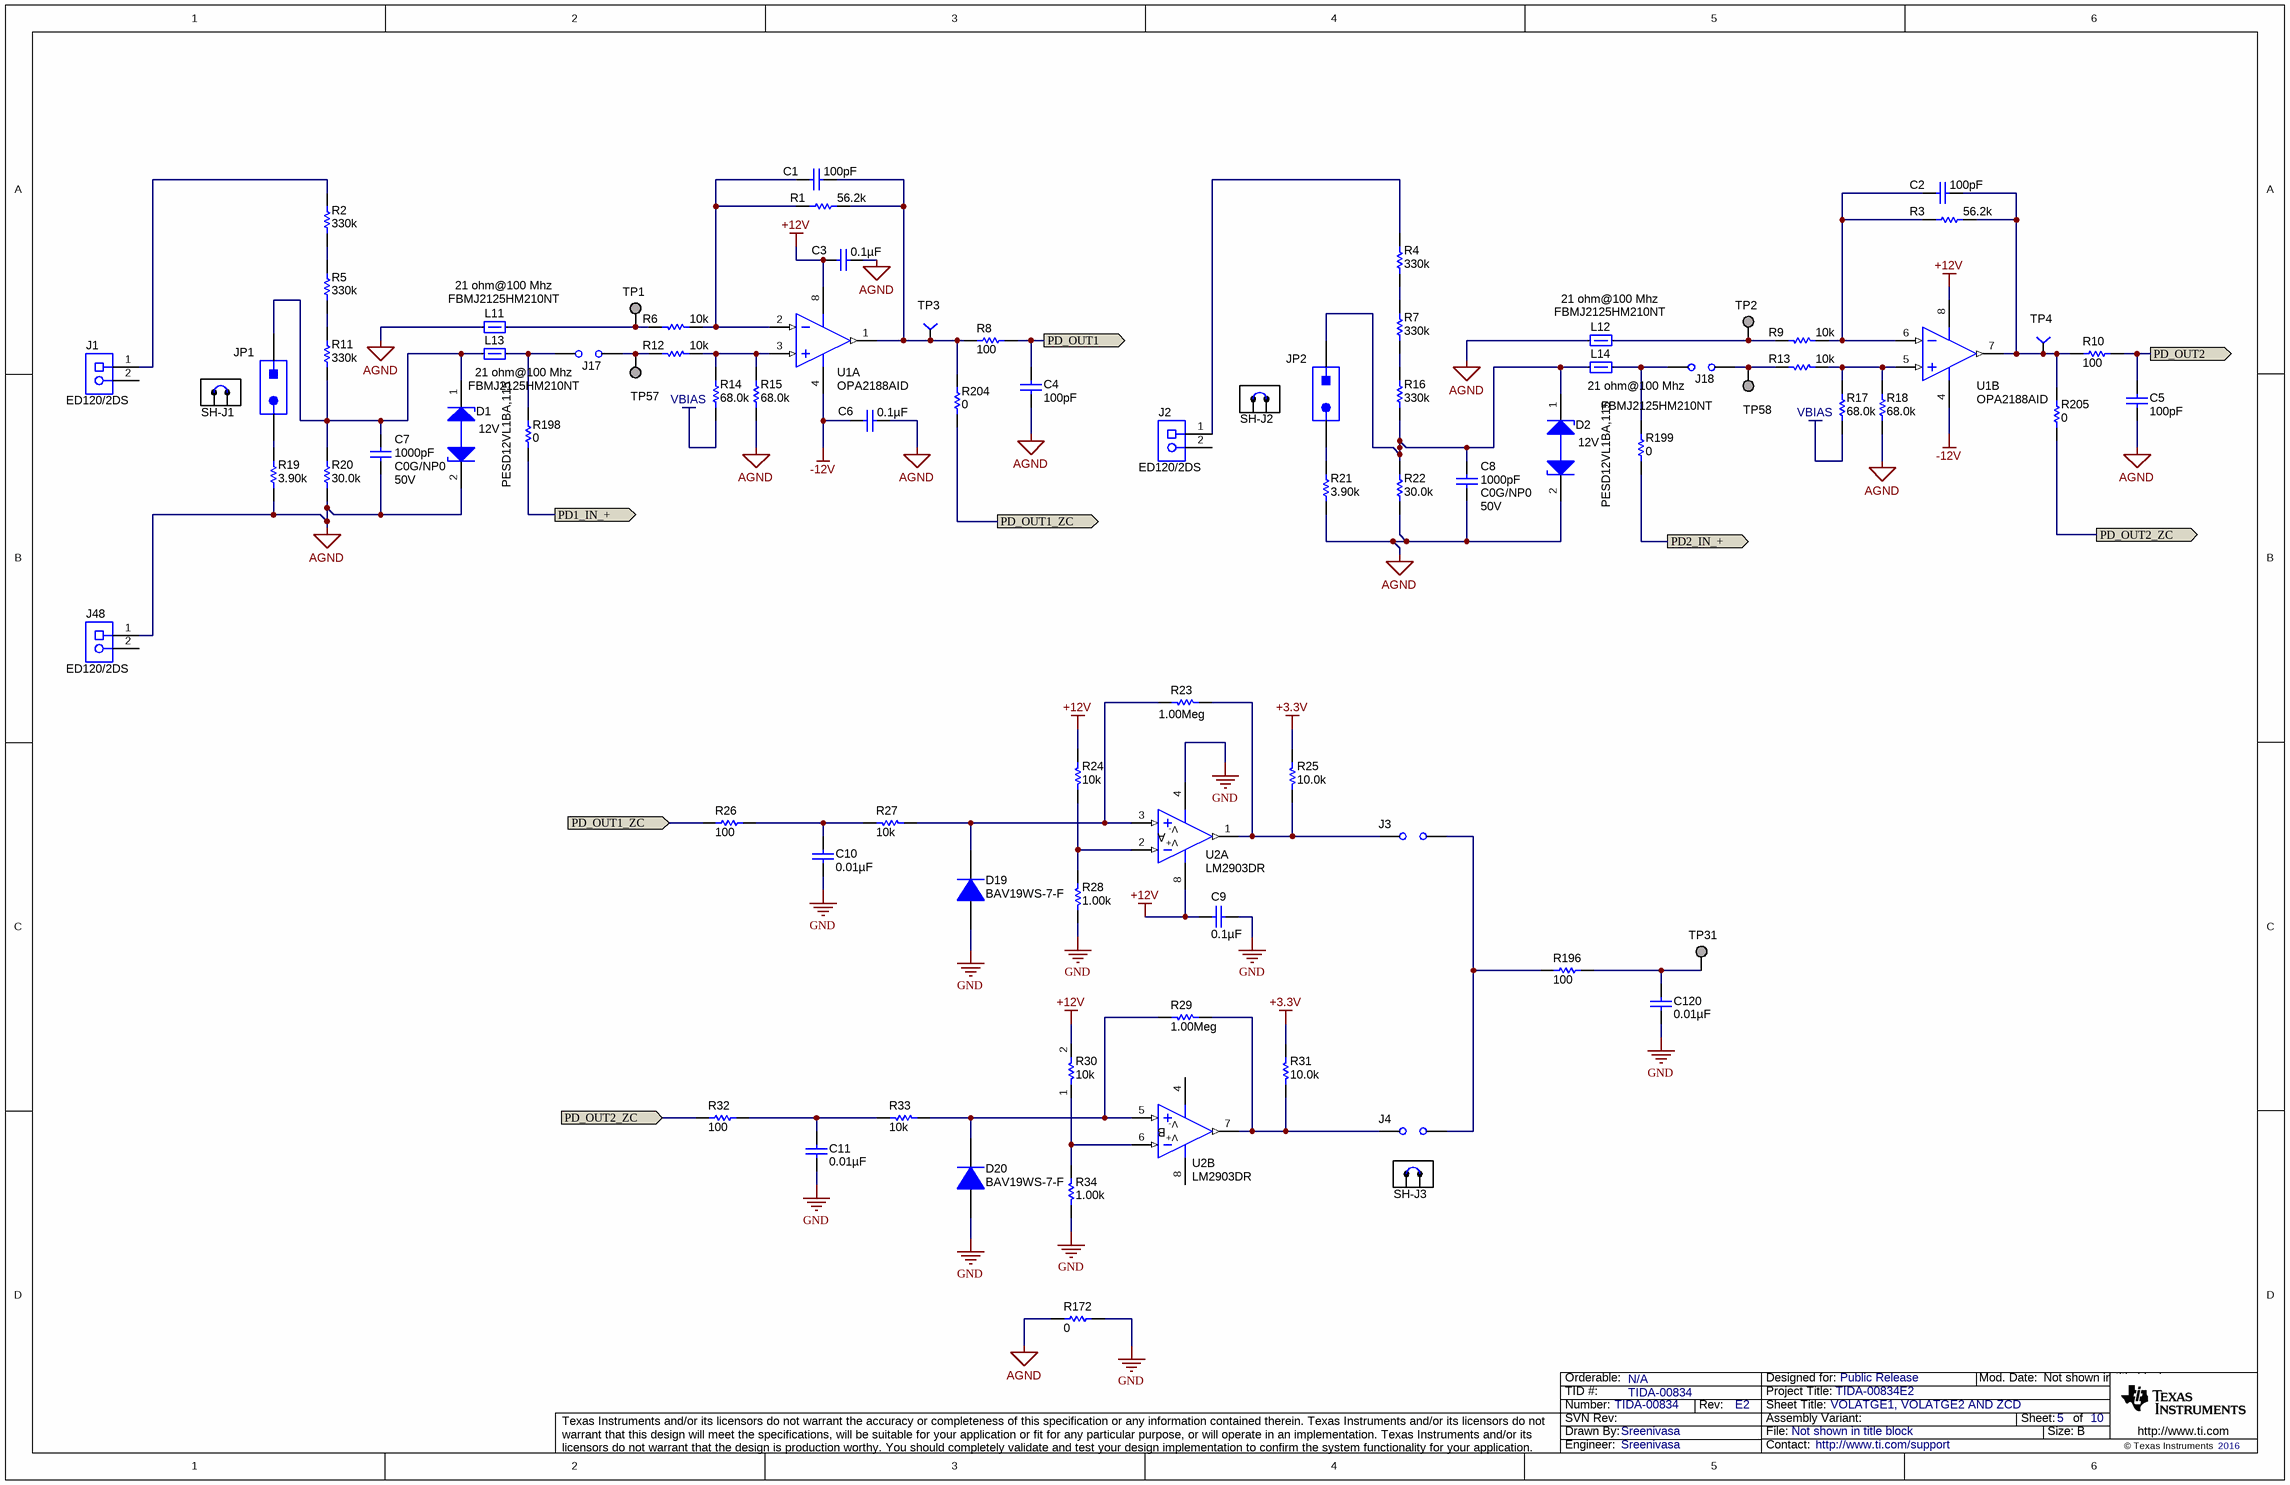
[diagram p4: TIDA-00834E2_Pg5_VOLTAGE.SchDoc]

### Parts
C1  ValueDisplayed: 100pF  [0603]  (hidden comment: 06033C101KAT2A)
C2  ValueDisplayed: 100pF  [0603]  (hidden comment: 06033C101KAT2A)
C3  ValueDisplayed: 0.1µF  [0603]  (hidden comment: 06033C104JAT2A)
C4  ValueDisplayed: 100pF  [0603]  (hidden comment: 06033C101KAT2A)
C5  ValueDisplayed: 100pF  [0603]  (hidden comment: 06033C101KAT2A)
C6  ValueDisplayed: 0.1µF  [0603]  (hidden comment: 06033C104JAT2A)
C7  ValueDisplayed: 1000pF  Value2: 50V  TempCo: C0G/NP0  [0603]  (hidden comment: C1608C0G1H102J080AA)
C8  ValueDisplayed: 1000pF  Value2: 50V  TempCo: C0G/NP0  [0603]  (hidden comment: C1608C0G1H102J080AA)
C9  ValueDisplayed: 0.1µF  [0603]  (hidden comment: 06033C104JAT2A)
C10  ValueDisplayed: 0.01µF  [0603]  (hidden comment: C1608C0G1E103J080AA)
C11  ValueDisplayed: 0.01µF  [0603]  (hidden comment: C1608C0G1E103J080AA)
C120  ValueDisplayed: 0.01µF  [0603]  (hidden comment: C1608C0G1E103J080AA)
D1  value 12V  [SOD-323]  (hidden comment: PESD12VL1BA,115)
D2  value 12V  [SOD-323]  (hidden comment: PESD12VL1BA,115)
D19  BAV19WS-7-F  [SOD-323]
D20  BAV19WS-7-F  [SOD-323]
J1  ED120/2DS  [CONN_ED120-2DS]
J2  ED120/2DS  [CONN_ED120-2DS]
J3  JUMPER_2X100MIL  [HDR100_1X2]  (value not drawn)
J4  JUMPER_2X100MIL  [HDR100_1X2]  (value not drawn)
J17  JUMPER_2X100MIL  [HDR100_1X2]  (value not drawn)
J18  JUMPER_2X100MIL  [HDR100_1X2]  (value not drawn)
J48  ED120/2DS  [CONN_ED120-2DS]
JP1  5-146280-2  [TSW-102-07-G-S]  (value not drawn)
JP2  5-146280-2  [TSW-102-07-G-S]  (value not drawn)
L11  value 21 ohm@100 Mhz  [0805_HV]  (hidden comment: FBMJ2125HM210NT)
L12  value 21 ohm@100 Mhz  [0805_HV]  (hidden comment: FBMJ2125HM210NT)
L13  value 21 ohm@100 Mhz  [0805_HV]  (hidden comment: FBMJ2125HM210NT)
L14  value 21 ohm@100 Mhz  [0805_HV]  (hidden comment: FBMJ2125HM210NT)
R1  ValueDisplayed: 56.2k  [0603]  (hidden comment: CRCW060356K2FKEA)
R2  ValueDisplayed: 330k  [1206]  (hidden comment: RC1206FR-07330KL)
R3  ValueDisplayed: 56.2k  [0603]  (hidden comment: CRCW060356K2FKEA)
R4  ValueDisplayed: 330k  [1206]  (hidden comment: RC1206FR-07330KL)
R5  ValueDisplayed: 330k  [1206]  (hidden comment: RC1206FR-07330KL)
R6  value 10k  [0603]  (hidden comment: CRCW060310K0FKEA)
R7  ValueDisplayed: 330k  [1206]  (hidden comment: RC1206FR-07330KL)
R8  value 100  [0603]  (hidden comment: CRCW0603100RFKEA)
R9  value 10k  [0603]  (hidden comment: CRCW060310K0FKEA)
R10  value 100  [0603]  (hidden comment: CRCW0603100RFKEA)
R11  ValueDisplayed: 330k  [1206]  (hidden comment: RC1206FR-07330KL)
R12  value 10k  [0603]  (hidden comment: CRCW060310K0FKEA)
R13  value 10k  [0603]  (hidden comment: CRCW060310K0FKEA)
R14  ValueDisplayed: 68.0k  [0603]  (hidden comment: RC0603FR-0768KL)
R15  ValueDisplayed: 68.0k  [0603]  (hidden comment: RC0603FR-0768KL)
R16  ValueDisplayed: 330k  [1206]  (hidden comment: RC1206FR-07330KL)
R17  ValueDisplayed: 68.0k  [0603]  (hidden comment: RC0603FR-0768KL)
R18  ValueDisplayed: 68.0k  [0603]  (hidden comment: RC0603FR-0768KL)
R19  ValueDisplayed: 3.90k  [0603]  (hidden comment: CRCW06033K90FKEA)
R20  ValueDisplayed: 30.0k  [0603]  (hidden comment: RC0603FR-0730KL)
R21  ValueDisplayed: 3.90k  [0603]  (hidden comment: CRCW06033K90FKEA)
R22  ValueDisplayed: 30.0k  [0603]  (hidden comment: RC0603FR-0730KL)
R23  value 1.00Meg  [0603]  (hidden comment: CRCW06031M00FKEA)
R24  value 10k  [0603]  (hidden comment: CRCW060310K0FKEA)
R25  value 10.0k  [0603]  (hidden comment: CRCW060310K0FKEA)
R26  value 100  [0603]  (hidden comment: CRCW0603100RFKEA)
R27  value 10k  [0603]  (hidden comment: CRCW060310K0FKEA)
R28  value 1.00k  [1206]  (hidden comment: CRCW12061K00FKEA)
R29  value 1.00Meg  [0603]  (hidden comment: CRCW06031M00FKEA)
R30  value 10k  [0603]  (hidden comment: CRCW060310K0FKEA)
R31  value 10.0k  [0603]  (hidden comment: CRCW060310K0FKEA)
R32  value 100  [0603]  (hidden comment: CRCW0603100RFKEA)
R33  value 10k  [0603]  (hidden comment: CRCW060310K0FKEA)
R34  value 1.00k  [1206]  (hidden comment: CRCW12061K00FKEA)
R172  value 0  [0805_HV]  (hidden comment: CRCW08050000Z0EA)
R196  value 100  [0603]  (hidden comment: CRCW0603100RFKEA)
R198  ValueDisplayed: 0  [0603]  (hidden comment: RC0603JR-070RL)
R199  ValueDisplayed: 0  [0603]  (hidden comment: RC0603JR-070RL)
R204  ValueDisplayed: 0  [0603]  (hidden comment: RC0603JR-070RL)
R205  ValueDisplayed: 0  [0603]  (hidden comment: RC0603JR-070RL)
SH-J1  881545-2  [TE_881545-2]  (value not drawn)  (mechanical)
SH-J2  881545-2  [TE_881545-2]  (value not drawn)  (mechanical)
SH-J3  881545-2  [TE_881545-2]  (value not drawn)  (mechanical)
TP1  Suggest using a net name here  [Keystone1573-2]  (value not drawn)
TP2  Suggest using a net name here  [Keystone1573-2]  (value not drawn)
TP3  TP-040_RND  [TP_H045P075]  (value not drawn)
TP4  TP-040_RND  [TP_H045P075]  (value not drawn)
TP31  Suggest using a net name here  [Keystone1573-2]  (value not drawn)
TP57  Suggest using a net name here  [Keystone1573-2]  (value not drawn)
TP58  Suggest using a net name here  [Keystone1573-2]  (value not drawn)
U1  OPA2188AID  [D0008A_N]  (parts A,B of 2)
U2  LM2903DR  [D0008A_N]  (parts A,B of 2)

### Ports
PD1_IN_+ (out), PD2_IN_+ (out), PD_OUT1 (out), PD_OUT1_ZC (in), PD_OUT1_ZC (out), PD_OUT2 (out), PD_OUT2_ZC (in), PD_OUT2_ZC (out)

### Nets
+3.3V: R25.2 R31.2
+12V: C3.2 C9.2 R24.2 R30.2 U1.8(V+) U2.8(V+)
-12V: C6.2 U1.4(V-)
AGND: C3.1 C4.2 C5.2 C6.1 C7.1 C8.1 D1.2(K) D2.2(K) J48.1 L11.1 L12.1 R15.1 R18.1 R19.1 R20.1 R21.1 R22.1 R172.1
GND: C9.1 C10.1 C11.1 C120.1 D19.2(A) D20.2(A) R28.1 R34.1 R172.2 U2.4(V-)
VBIAS: R14.1 R17.1
PD1_IN_+: R198.1 ; port PD1_IN_+
PD2_IN_+: R199.1 ; port PD2_IN_+
PD_OUT1: C4.1 R8.2 ; port PD_OUT1
PD_OUT1_ZC: R26.1 R204.1 ; port PD_OUT1_ZC
PD_OUT2: C5.1 R10.2 ; port PD_OUT2
PD_OUT2_ZC: R32.1 R205.1 ; port PD_OUT2_ZC
NetC1_1: C1.1 R1.2 R6.1 U1.2(IN_A-)
NetC1_2: C1.2 R1.1 R8.1 R204.2 TP3.1 U1.1(OUT_A)
NetC2_1: C2.1 R3.2 R9.1 U1.6(IN_B-)
NetC2_2: C2.2 R3.1 R10.1 R205.2 TP4.1 U1.7(OUT_B)
NetC7_2: C7.2 D1.1(K) JP1.1 L13.1 R11.1 R20.2
NetC8_2: C8.2 D2.1(K) JP2.1 L14.1 R16.1 R22.2
NetC10_2: C10.2 R26.2 R27.1
NetC11_2: C11.2 R32.2 R33.1
NetC120_2: C120.2 R196.2 TP31.1
NetD19_1: D19.1(K) R23.2 R27.2 U2.3(IN+)
NetD20_1: D20.1(K) R29.2 R33.2 U2.5(IN+)
NetJ1_1: J1.1 R2.2
NetJ2_1: J2.1 R4.2
NetJ3_1: J3.1 R23.1 R25.1 U2.1(OUT)
NetJ3_2: J3.2 J4.2 R196.1
NetJ4_1: J4.1 R29.1 R31.1 U2.7(OUT)
NetJ17_1: J17.1 R12.2 TP57.1
NetJ17_2: J17.2 L13.2 R198.2
NetJ18_1: J18.1 R13.2 TP58.1
NetJ18_2: J18.2 L14.2 R199.2
NetJP1_2: JP1.2 R19.2
NetJP2_2: JP2.2 R21.2
NetL11_2: L11.2 R6.2 TP1.1
NetL12_2: L12.2 R9.2 TP2.1
NetR2_1: R2.1 R5.2
NetR4_1: R4.1 R7.2
NetR5_1: R5.1 R11.2
NetR7_1: R7.1 R16.2
NetR12_1: R12.1 R14.2 R15.2 U1.3(IN_A+)
NetR13_1: R13.1 R17.2 R18.2 U1.5(IN_B+)
NetR24_1: R24.1 R28.2 U2.2(IN-)
NetR30_1: R30.1 R34.2 U2.6(IN-)

Not connected (* = marked no-connect by the designer): J1 2; J2 2; J48 2

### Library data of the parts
C1 C2 C4 C5 = 06033C101KAT2A: as C19 on sheet TIDA-00834E2_Pg3_CT1_CT2
C3 C6 C9 = 06033C104JAT2A: CAP, CERM, 0.1uF, 25V, +/-5%, X7R, 0603; Manufacturer: AVX; Polarized: N; CompType: Capacitor; U/M: EA; Cap_F: 0.0000001; Tolerance_%: 5; ESR_Ohm: 0.05; Value1: 0.05 ohm; VDC_V: 25; TaMin_C: -55; TaMax_C: 125
C7 C8 = C1608C0G1H102J: CAP, CERM, 1000pF, 50V, +/-5%, C0G/NP0, 0603; Manufacturer: TDK; Polarized: N; CompType: Capacitor; U/M: EA; Cap_F: 0.000000001; Tolerance_%: 5; ESR_Ohm: 0.0563; Value1: 0.0563 ohm; VDC_V: 50; TaMin_C: -55; TaMax_C: 125
C10 C11 C120 = C1608C0G1E103J: CAP, CERM, 0.01uF, 25V, +/-5%, C0G/NP0, 0603; Manufacturer: TDK; Polarized: N; CompType: Capacitor; U/M: EA; Cap_F: 0.00000001; Tolerance_%: 5; Value1: Unknown; VDC_V: 25; TaMin_C: -55; TaMax_C: 125
D1 D2 = PESD3V3L1BA: as D3 on sheet TIDA-00834E2_Pg3_CT1_CT2
D19 D20 = BAV19WS-7-F: Diode, Switching, 100 V, 0.2 A, SOD-323; Manufacturer: Diodes Inc.; U/M: EA; Vf_V: 1.25; Value: 100V; Value1: 0.2A; Value2: 1.25V; Io_A: 0.2; Vr_V: 100; TJmax_C: 150; SizeAreaWB_mm2: 8.695; SizeArea_mm2: 3.645; SizeX_mm: 2.7; SizeY_mm: 1.35; SizeZ_mm: 1; AEC Category: Q101
J1 J2 J48 = ED120/2DS: TERMINAL BLOCK 5.08MM VERT 2POS, TH; Manufacturer: On-Shore Technology; SymbolCreator: a0412235; U/M: EA
J3 J4 J17 J18 = JUMPER_2X100MIL: as J19 on sheet TIDA-00834E2_Pg3_CT1_CT2
JP1 JP2 = TSW-102-07-G-S: as JP3 on sheet TIDA-00834E2_Pg3_CT1_CT2
L11-L14 = FBMJ2125HM210NT: as L1 on sheet TIDA-00834E2_Pg3_CT1_CT2
R1 R3 = CRCW060356K2FKEA: RES, 56.2 k, 1%, 0.1 W, 0603; Manufacturer: Vishay-Dale; CompType: Resistor; Value: 56.2k; Res_ohm: 56200; Value_Code: 56k2; Tolerance_%: 1; Power_W: 0.1; Value2: 0.1W; VDC_V: 75; TempCo: 100 ppm/C; SizeArea_mm2: 1.28; SizeX_mm: 1.6; SizeY_mm: 0.8; EIA_Code: E96; U/M: EA; AEC Category: Q200
R2 R4 R5 R7 R11 R16 = RC1206FR-07330KL: RES, 330 k, 1%, 0.25 W, 1206; Manufacturer: Yageo America; CompType: Resistor; Value: 330k; Res_ohm: 330000; Tolerance_%: 1; Power_W: 0.25; Value2: 0.25W; VDC_V: 200; TempCo: 100 ppm/C; U/M: EA
R6 R9 R12 R13 R24 R27 R30 R33 = RNCF0603TKY10K0: RES, 10.0k ohm, 1%, 0.1W, 0603; Manufacturer: Stackpole Electronics Inc; CompType: Resistor; Res_ohm: 10000; Value_Code: 10k0; Tolerance_%: 0.01; Value1: 0.01%; Power_W: 0.063; Value2: 0.063W; VDC_V: 50; TempCo: 5 ppm/C; U/M: EA
R8 R10 R26 R32 R196 = CRCW0603100RFKEA: as R45 on sheet TIDA-00834E2_Pg3_CT1_CT2
R14 R15 R17 R18 = RC0603FR-0768KL: RES, 68.0 k, 1%, 0.1 W, 0603; Manufacturer: Yageo America; CompType: Resistor; Value: 68.0k; Res_ohm: 68000; Value_Code: 68k0; Tolerance_%: 1; Power_W: 0.1; Value2: 0.1W; VDC_V: 150; TempCo: 200 ppm/C; SizeArea_mm2: 1.28; SizeX_mm: 1.6; SizeY_mm: 0.8; U/M: EA; AEC Category: Q200
R19 R21 = CRCW06033K90FKEA: RES, 3.90 k, 1%, 0.1 W, 0603; Manufacturer: Vishay-Dale; CompType: Resistor; Value: 3.90k; Res_ohm: 3900; Value_Code: 3k90; Tolerance_%: 1; Power_W: 0.1; Value2: 0.1W; TempCo: 100 ppm/C; SizeArea_mm2: 1.28; SizeX_mm: 1.6; SizeY_mm: 0.8; U/M: EA; AEC Category: Q200
R20 R22 = RC0603FR-0730KL: RES, 30.0 k, 1%, 0.1 W, 0603; Manufacturer: Yageo America; CompType: Resistor; Value: 30.0k; Res_ohm: 30000; Value_Code: 30k0; Tolerance_%: 1; Power_W: 0.1; Value2: 0.1W; VDC_V: 150; TempCo: 200 ppm/C; SizeArea_mm2: 1.28; SizeX_mm: 1.6; SizeY_mm: 0.8; U/M: EA; AEC Category: Q200
R23 R29 = CRCW06031M00FKEA: RES, 1.00Meg ohm, 1%, 0.1W, 0603; Manufacturer: Vishay-Dale; CompType: Resistor; Res_ohm: 1000000; Value_Code: 1M00; Tolerance_%: 1; Power_W: 0.1; VDC_V: 75; TempCo: 100 ppm/C; EIA_Code: E96; U/M: EA
R25 R31 = CRCW060310K0FKEA: RES, 10.0k ohm, 1%, 0.1W, 0603; Manufacturer: Vishay-Dale; CompType: Resistor; Res_ohm: 10000; Value_Code: 10k0; Tolerance_%: 1; Power_W: 0.1; VDC_V: 75; TempCo: 100 ppm/C; EIA_Code: E96; U/M: EA
R28 R34 = CRCW12061K00FKEA: RES, 1.00k ohm, 1%, 0.25W, 1206; Manufacturer: Vishay-Dale; CompType: Resistor; Res_ohm: 1000; Value_Code: 1k00; Tolerance_%: 1; Power_W: 0.25; VDC_V: 200; TempCo: 100 ppm/C; EIA_Code: E96; U/M: EA
R172 = CRCW0805330KJNEA: RES, 0 ohm, 5%, 0.125W, 0805; Manufacturer: Vishay-Dale; CompType: Resistor; Tolerance_%: 5; Power_W: 0.125; VDC_V: 150; TempCo: 200 ppm/C; EIA_Code: E24; U/M: EA
R198 R199 R204 R205 = RC0603JR-070RL: as R42 on sheet TIDA-00834E2_Pg3_CT1_CT2
SH-J1-SH-J3 = 881545-2: as SH-J4 on sheet TIDA-00834E2_Pg3_CT1_CT2
TP1 TP2 TP31 TP57 TP58 = 1573-2: as TP5 on sheet TIDA-00834E2_Pg3_CT1_CT2
TP3 TP4 = TP-040_RND: as TP10 on sheet TIDA-00834E2_Pg3_CT1_CT2
U1 = OPA2188AID: as U4 on sheet TIDA-00834E2_Pg3_CT1_CT2
U2 = LM2903D: Dual Comparator, D0008A; Manufacturer: Texas Instruments; CompType: OpAmp IC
